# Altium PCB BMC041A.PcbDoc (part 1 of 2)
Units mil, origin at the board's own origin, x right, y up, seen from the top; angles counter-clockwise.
Board outline 3850 x 3650 mil, 6 copper layers (Top Layer, MidLayer1, MidLayer2, MidLayer3, MidLayer4, Bottom Layer), stack 62.8 mil thick; 106 components, 43 nets, 241 pads, 352 vias.
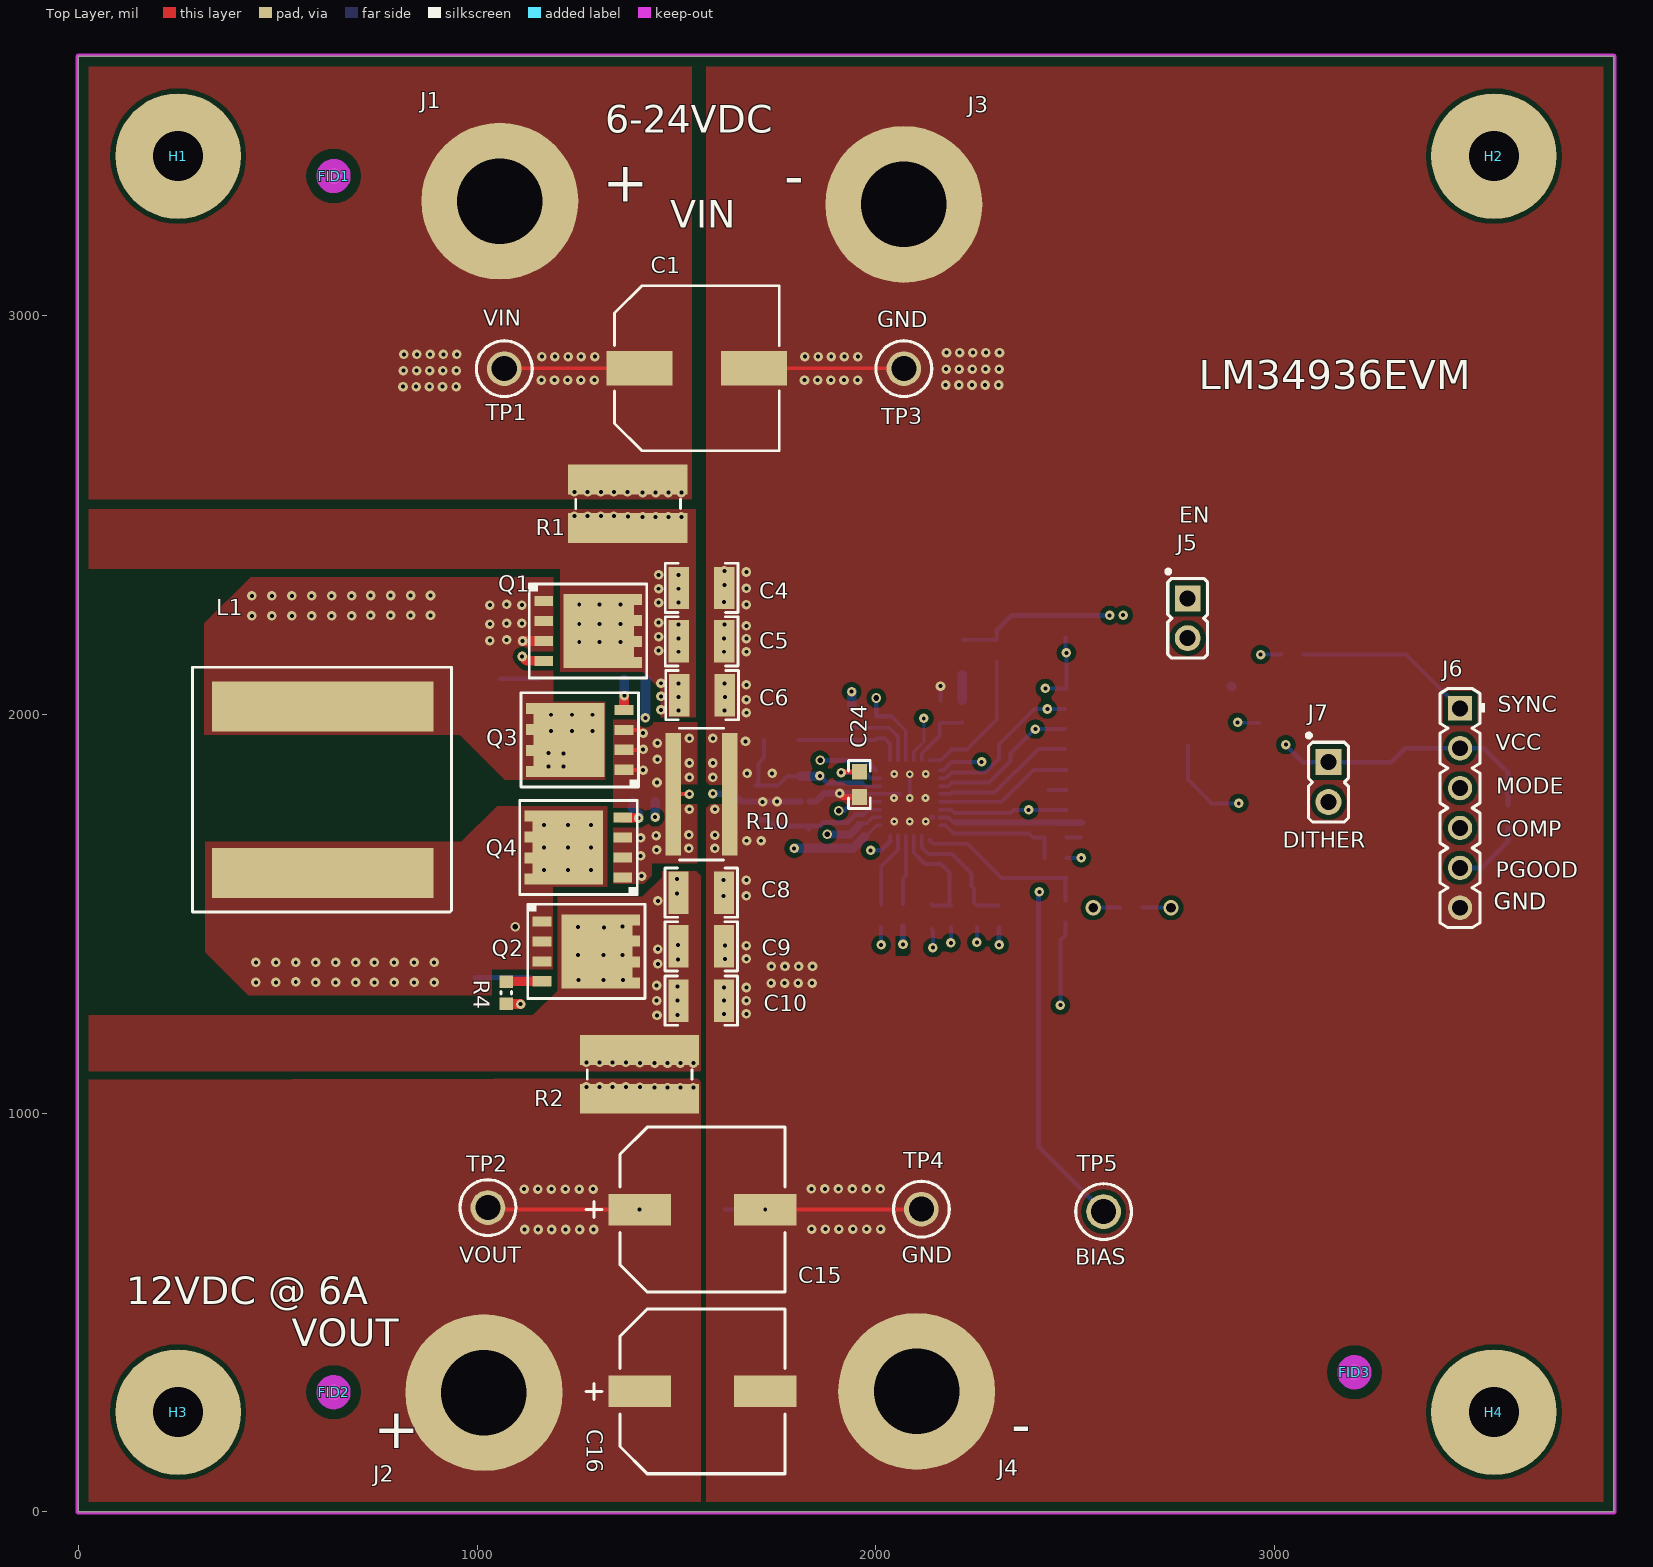
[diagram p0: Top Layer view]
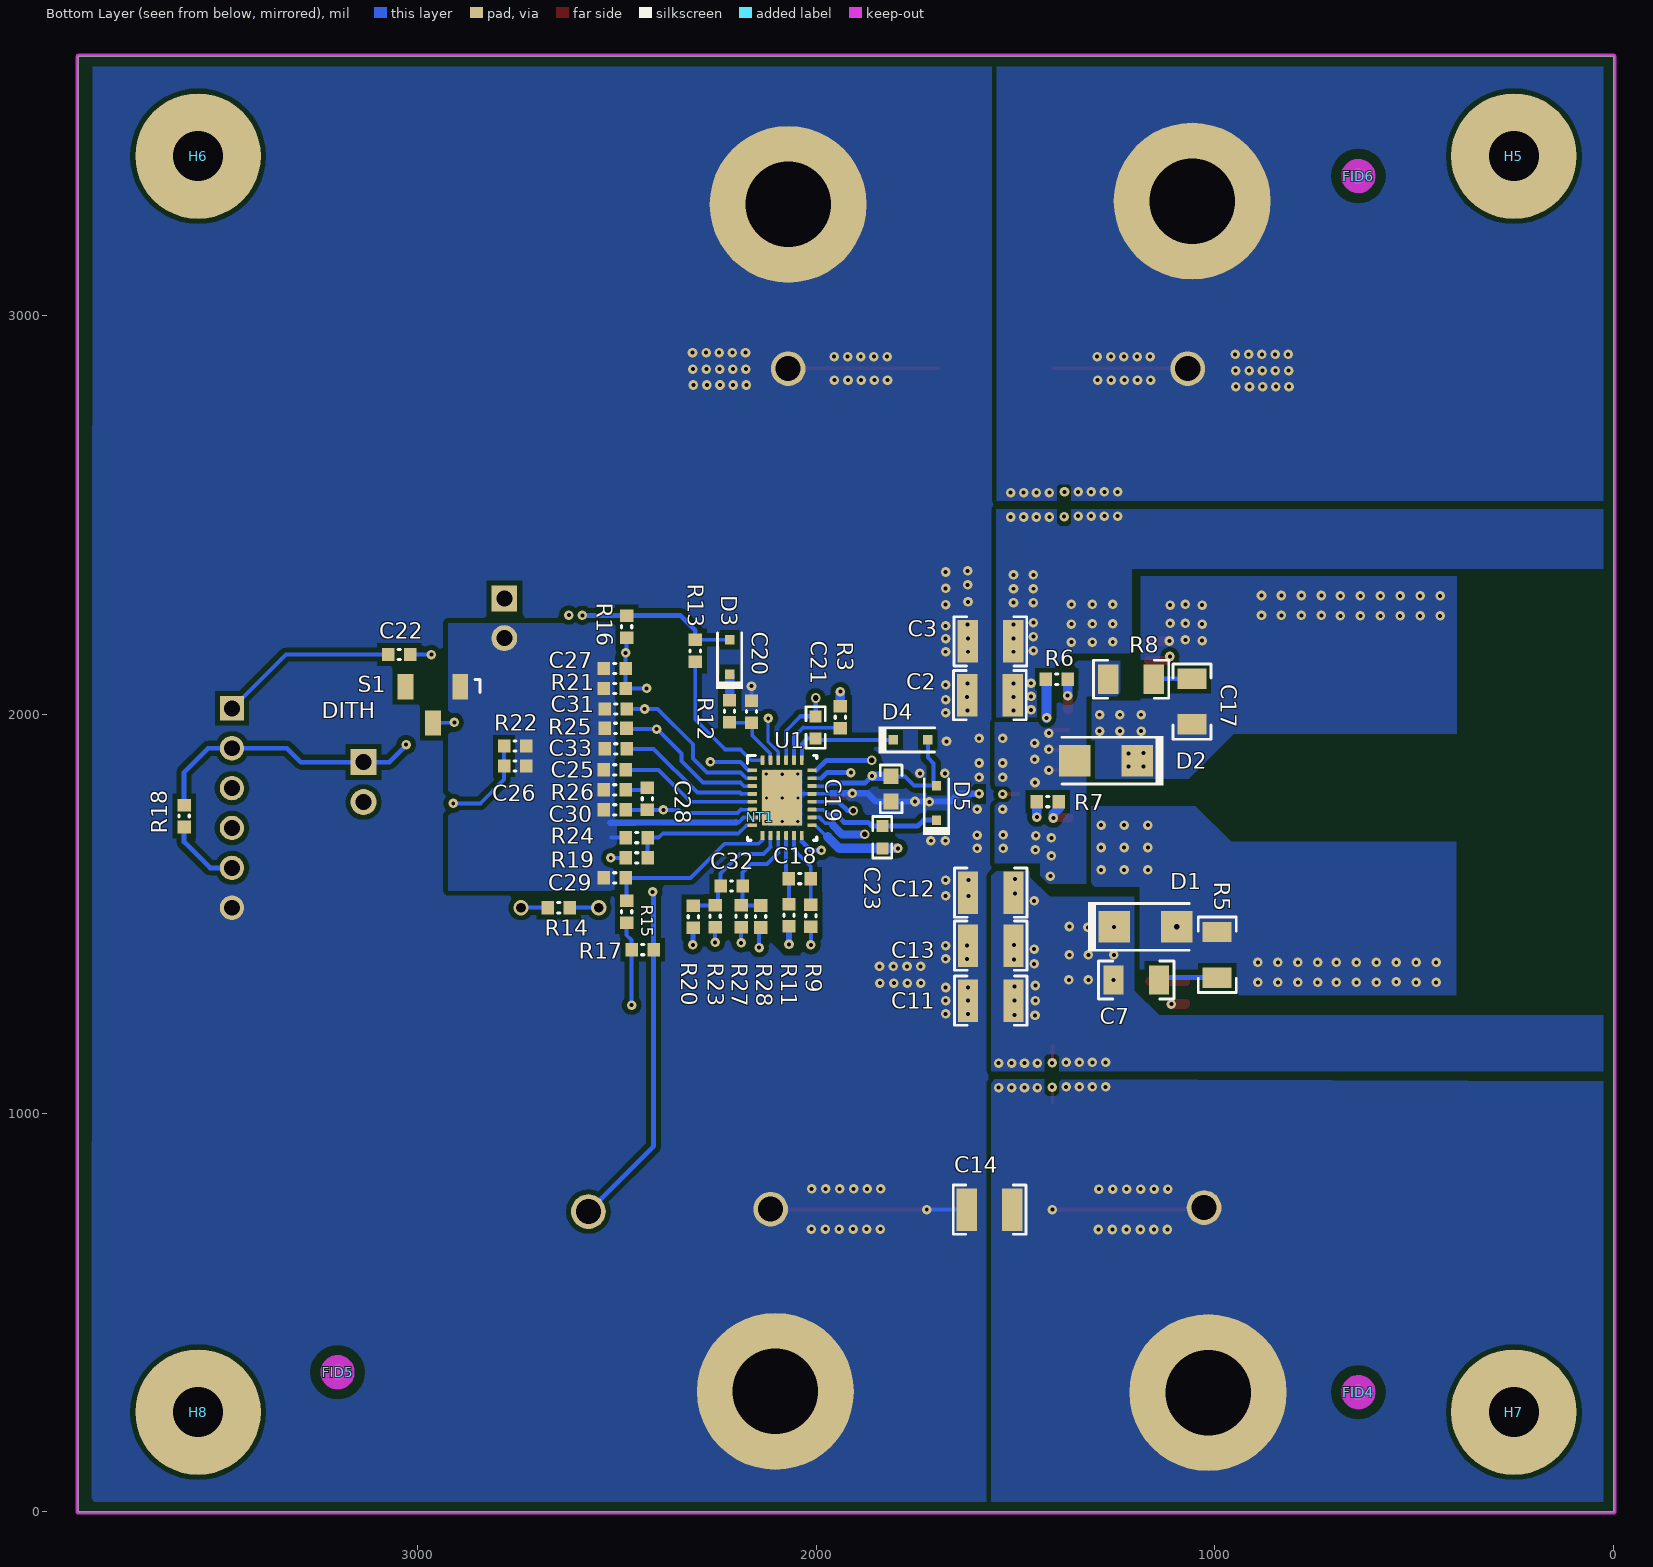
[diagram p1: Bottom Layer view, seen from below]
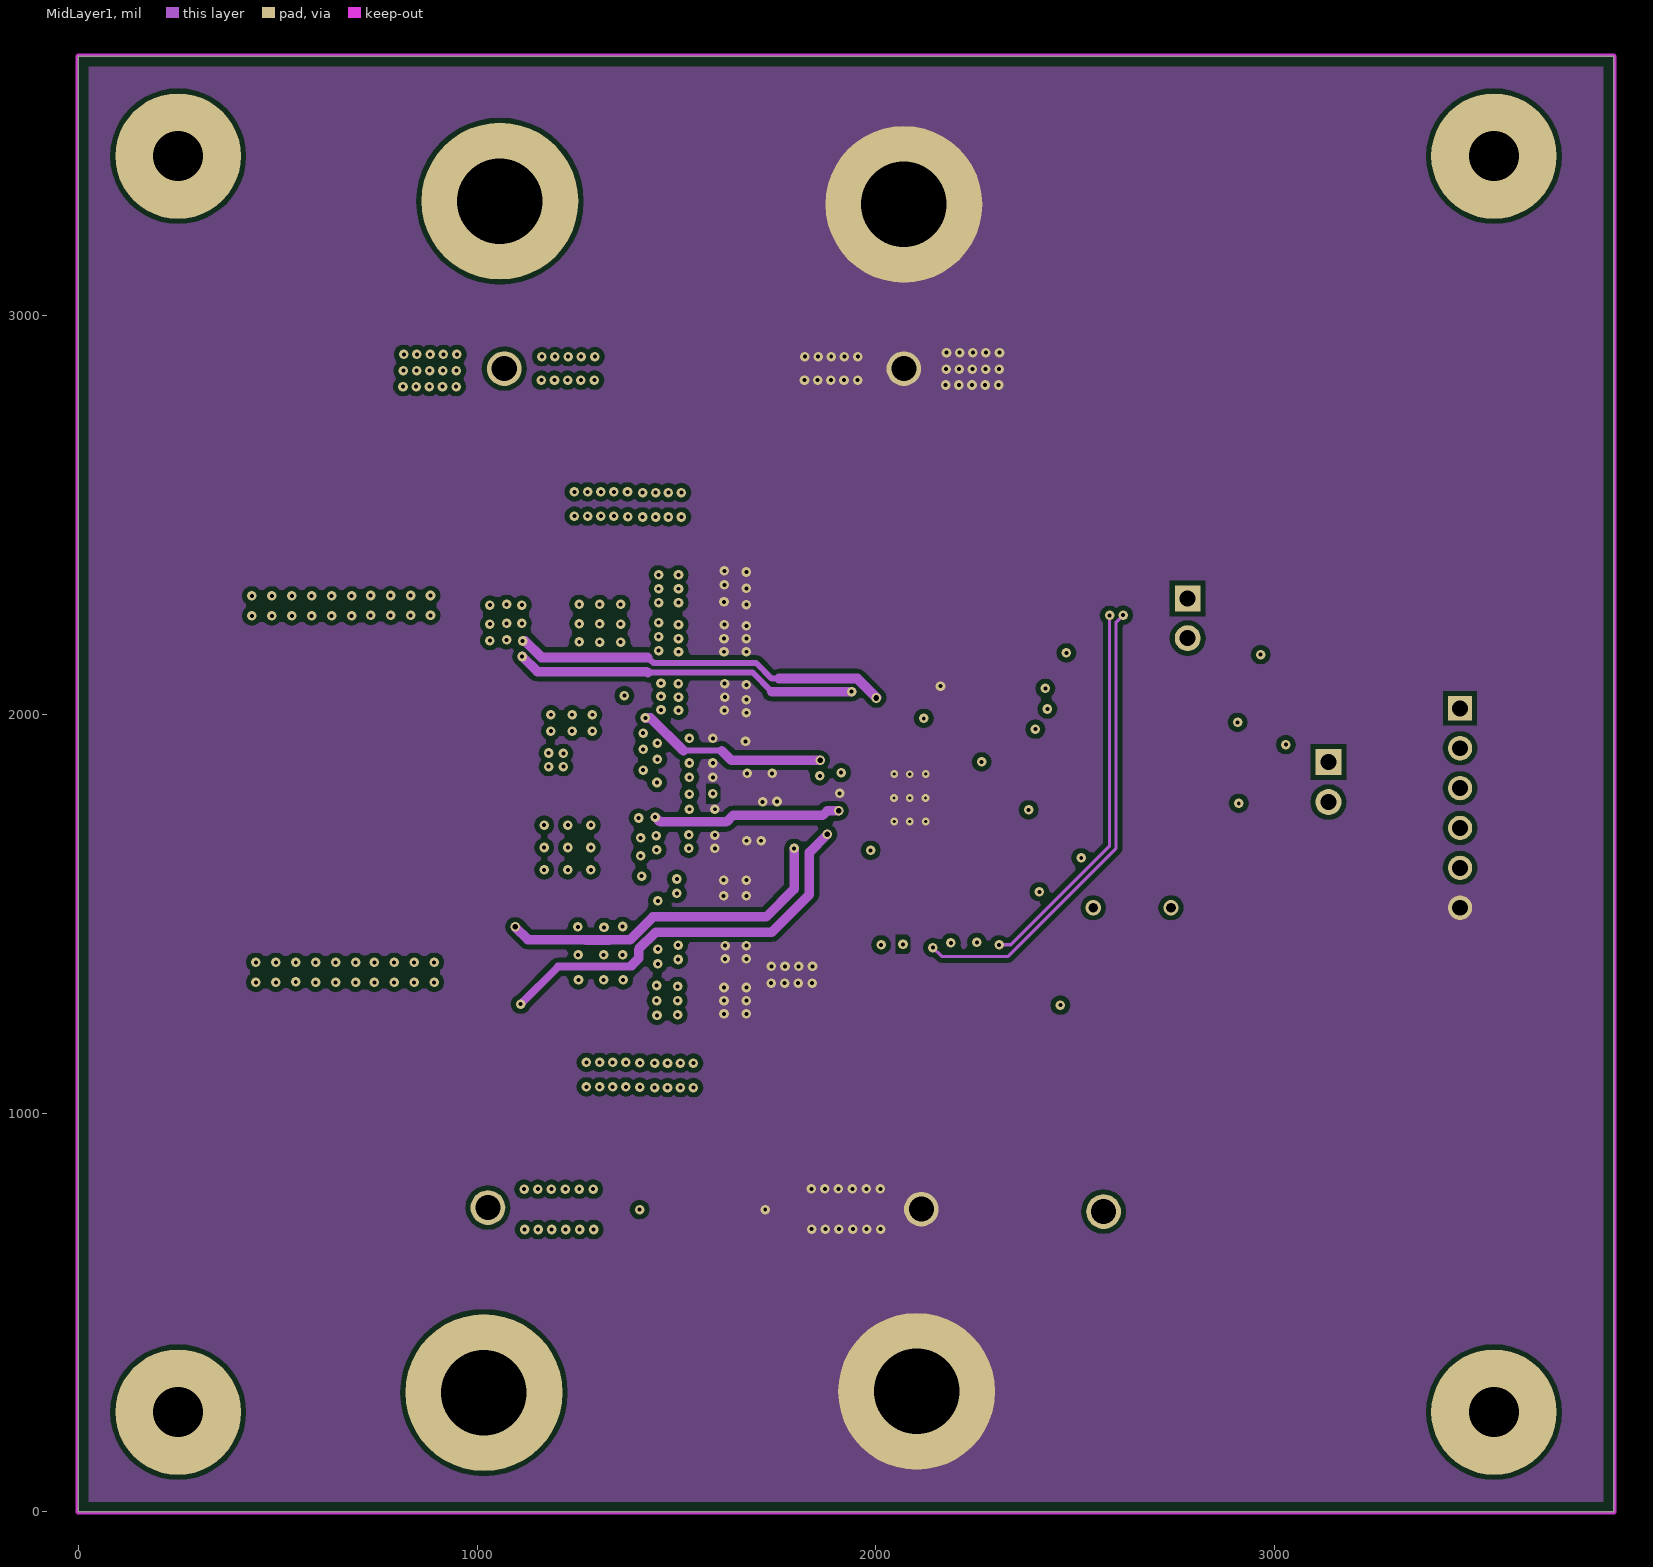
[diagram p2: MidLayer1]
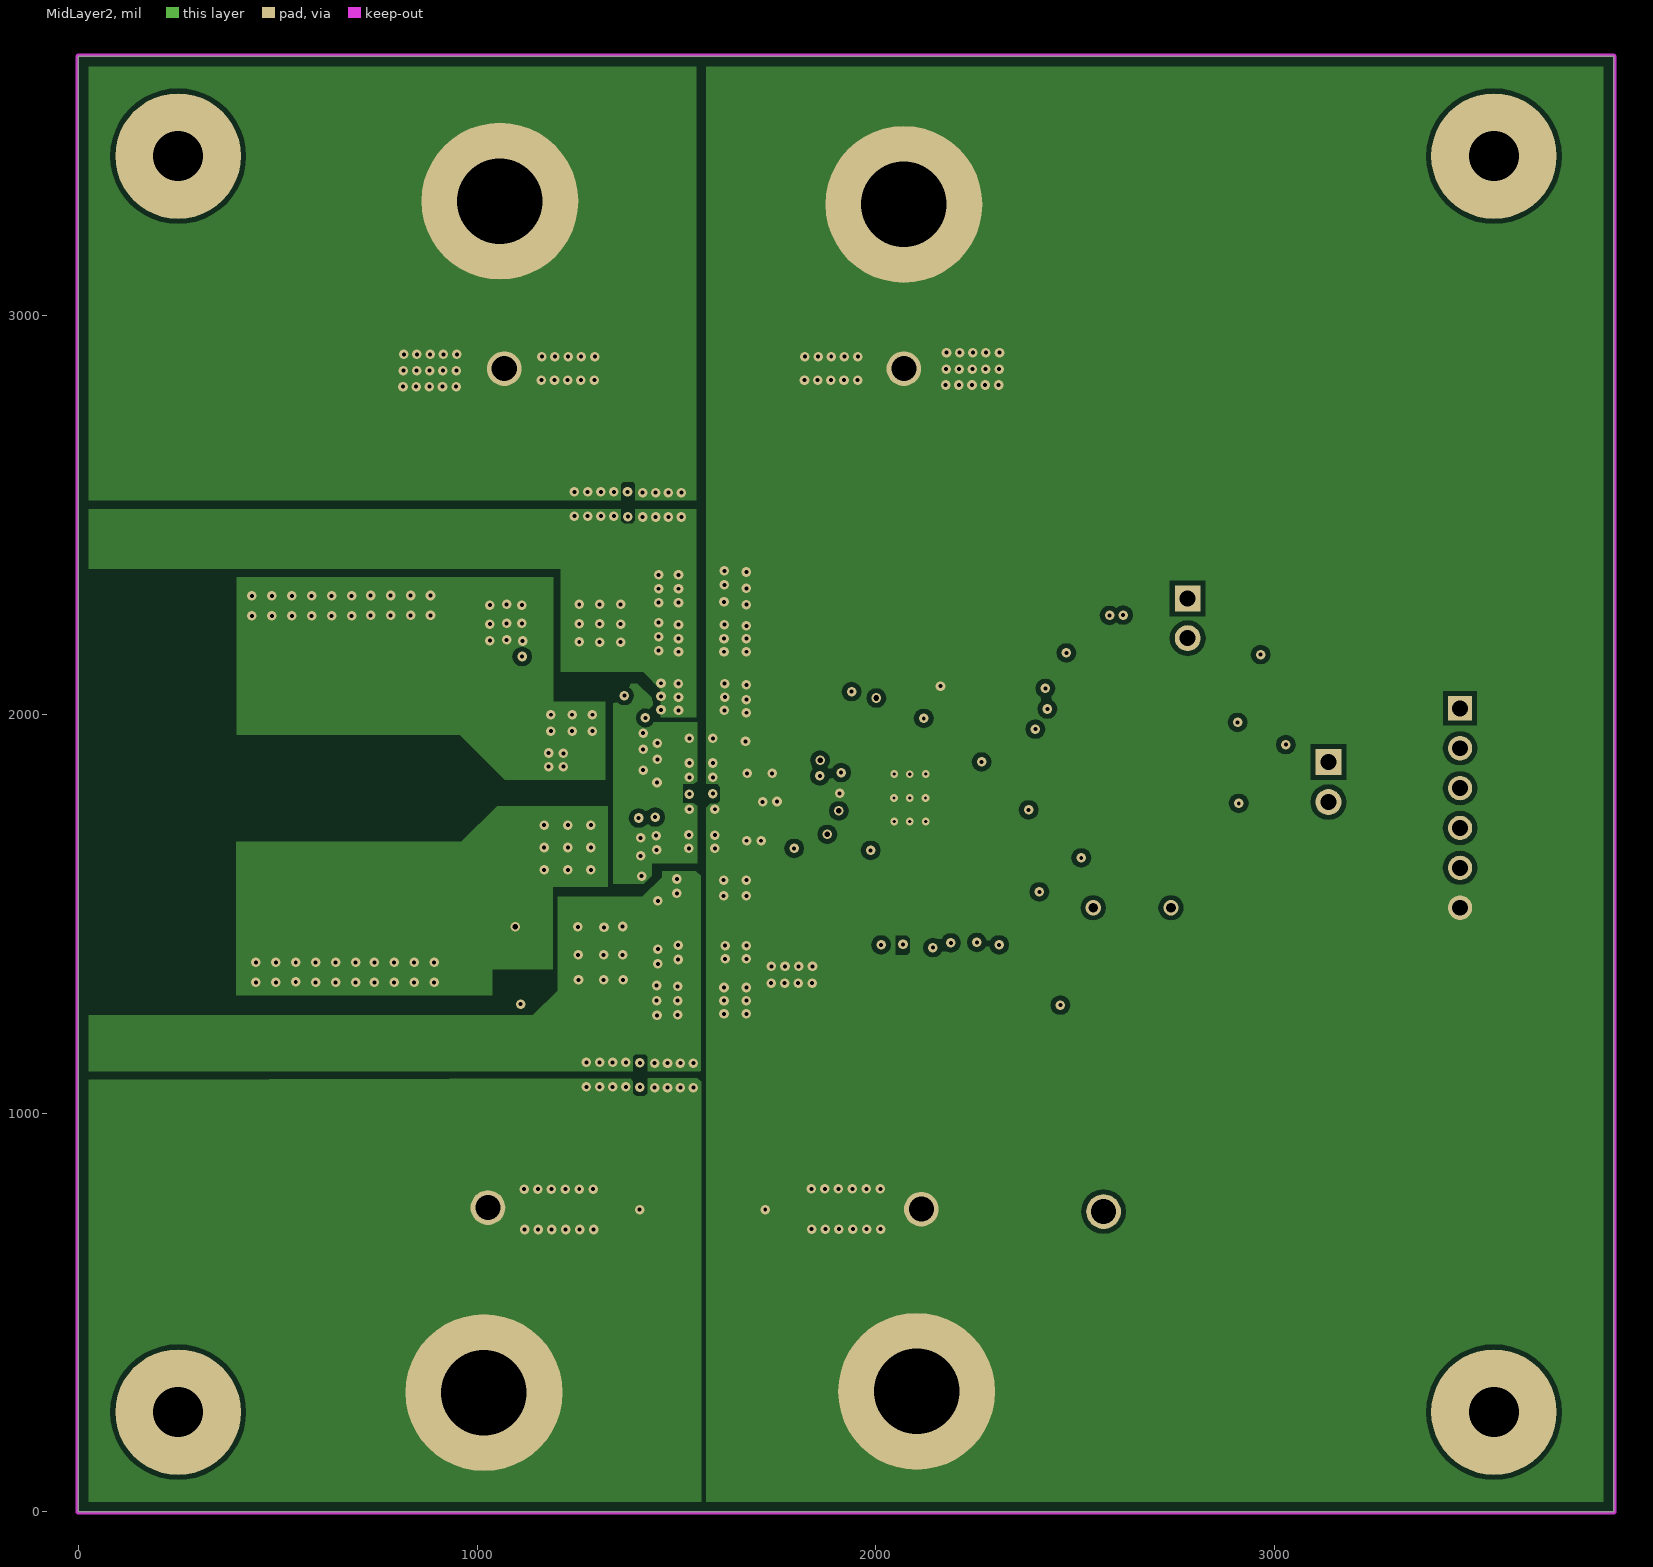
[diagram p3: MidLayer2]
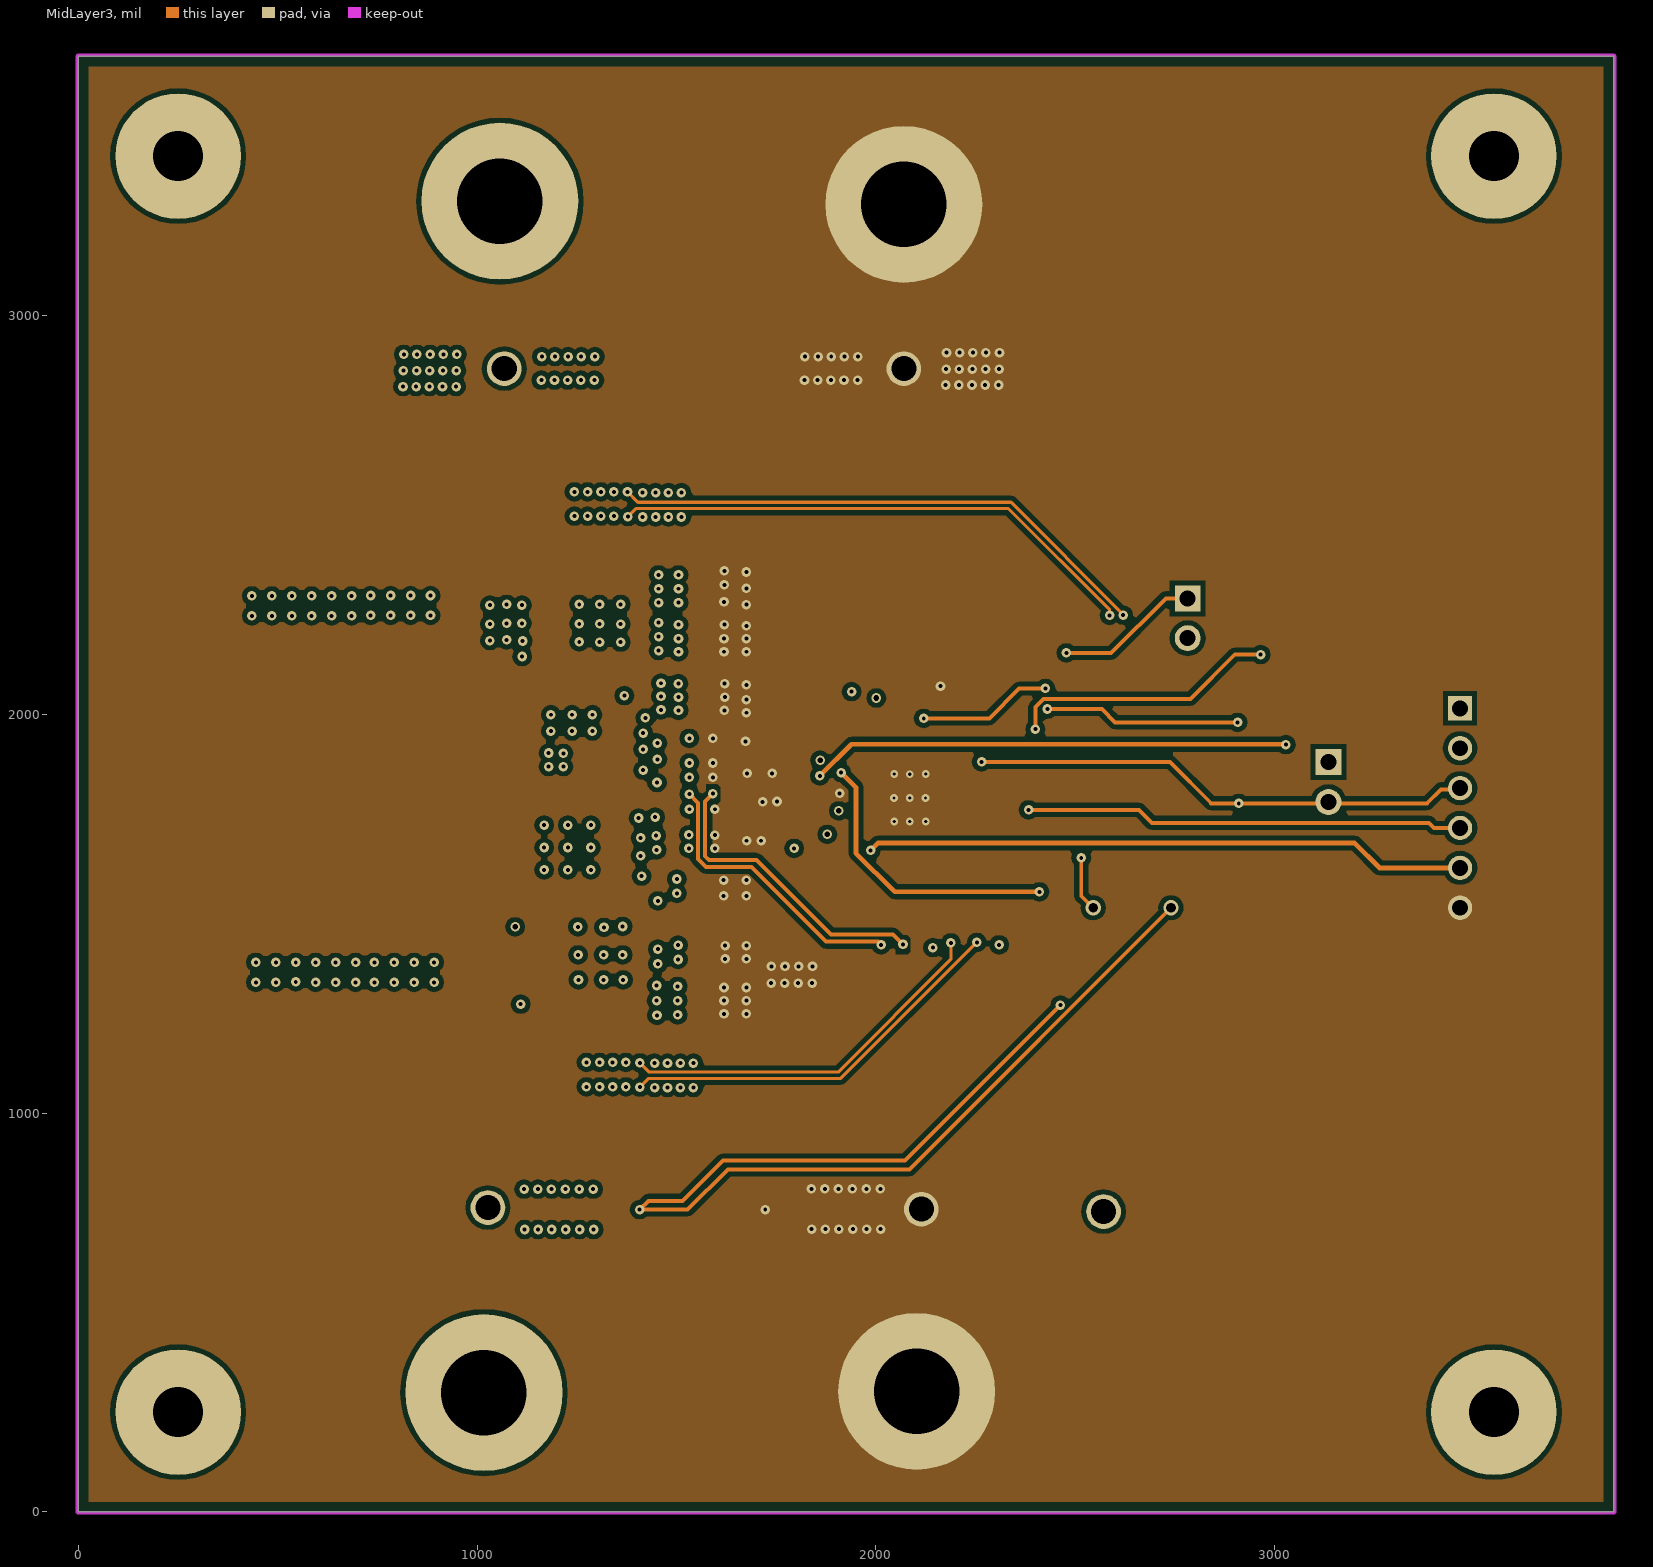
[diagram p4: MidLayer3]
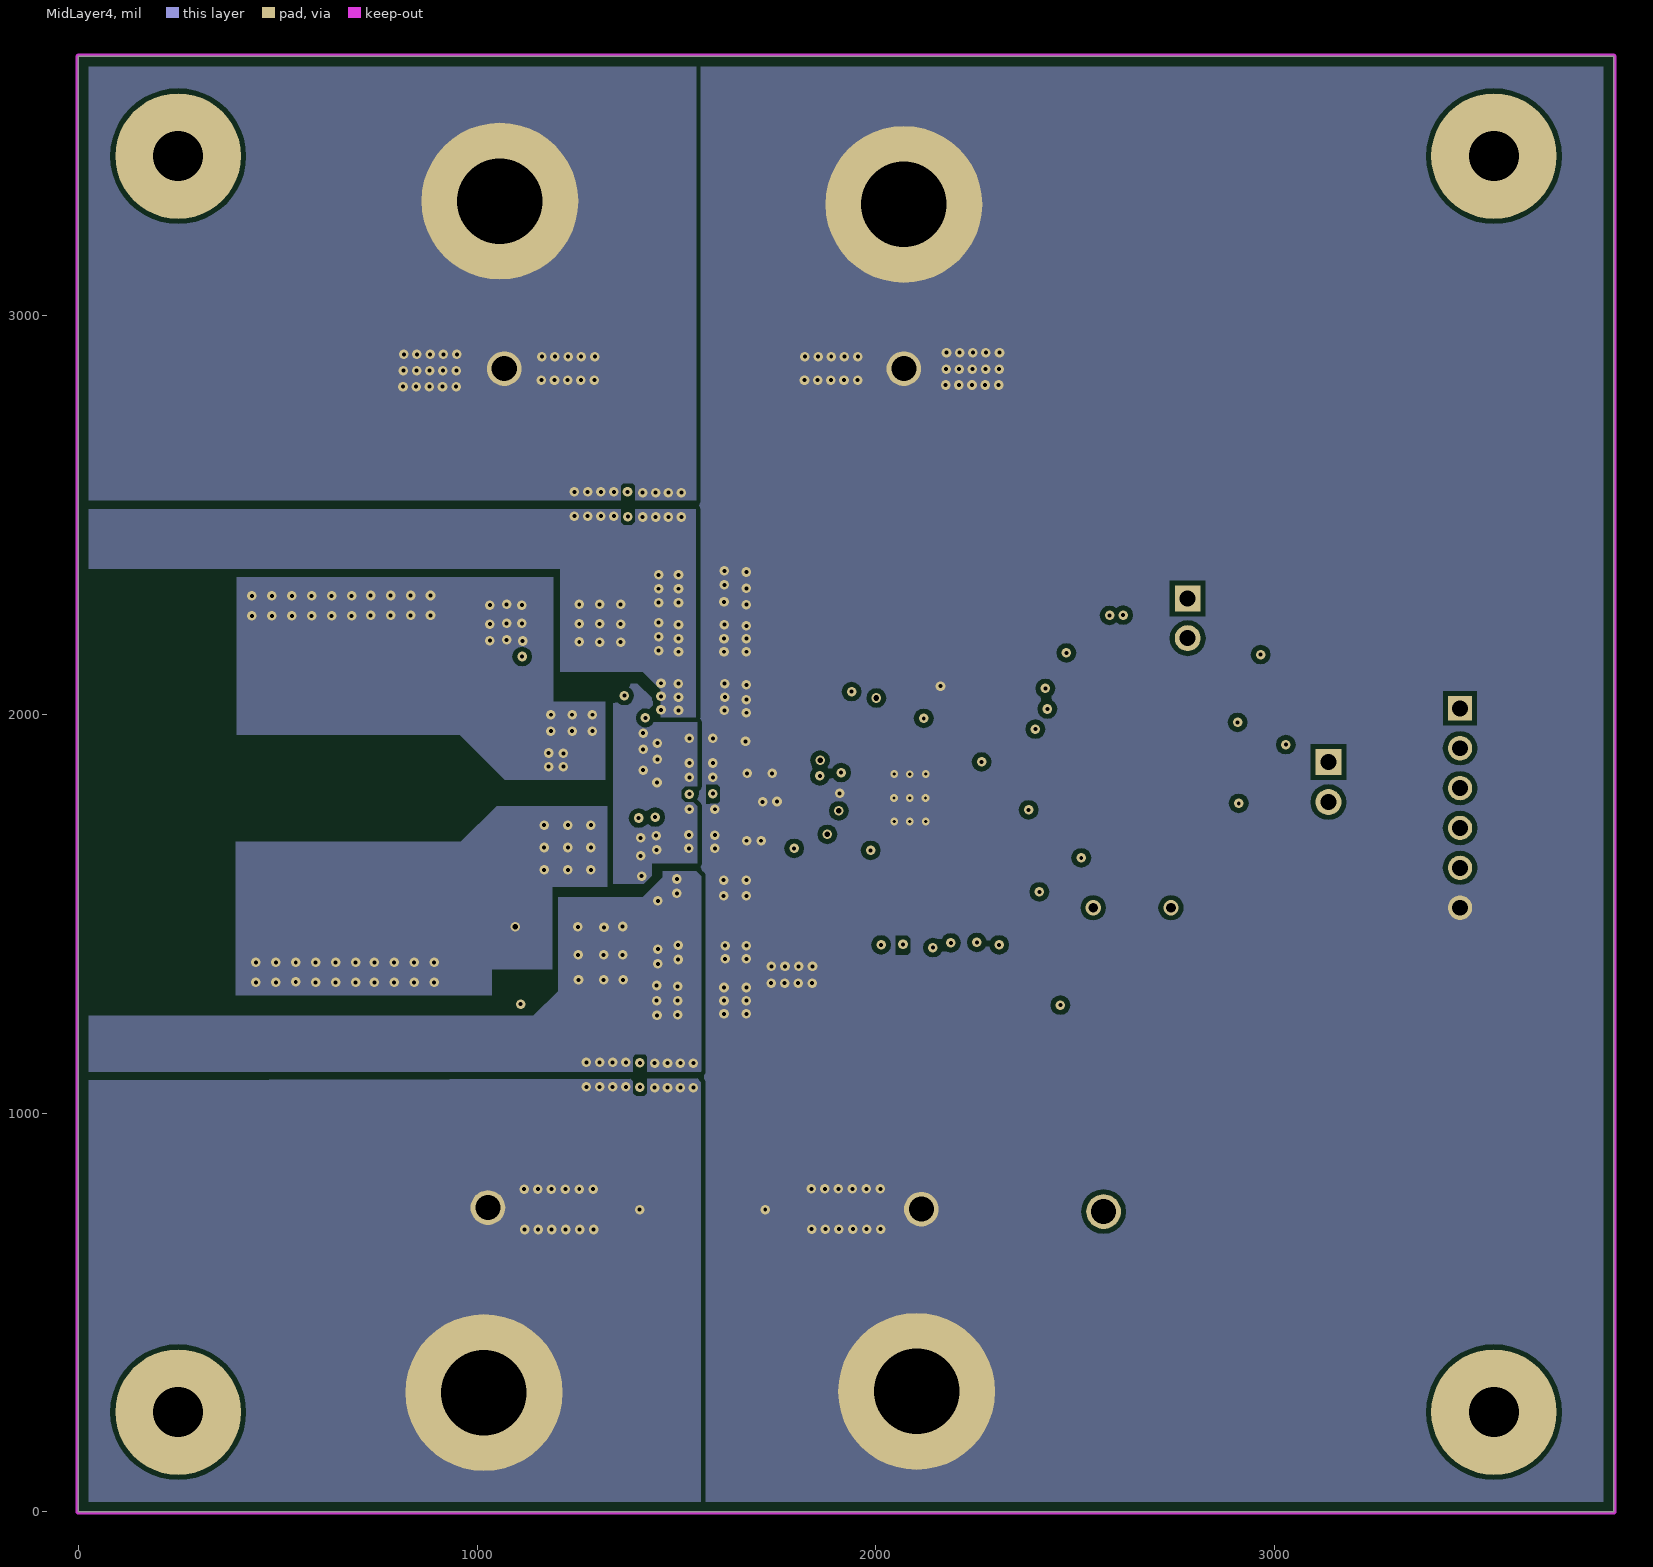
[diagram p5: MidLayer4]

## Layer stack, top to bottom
Top Solder: solder mask 0.4, Solder Resist, Dk 3.5
Top Layer: signal copper 2.8
Dielectric1: prepreg 8, FR-4, Dk 4.2
MidLayer1: signal copper 2.8
Dielectric2: prepreg 10, FR-4, Dk 4.8
MidLayer2: signal copper 2.8
Dielectric3: core 10, FR-4, Dk 4.2
MidLayer3: signal copper 2.8
Dielectric4: prepreg 10, FR-4, Dk 4.8
MidLayer4: signal copper 2.8
Dielectric5: prepreg 8, FR-4, Dk 4.2
Bottom Layer: signal copper 2.8
Bottom Solder: solder mask 0.4, Solder Resist, Dk 3.5

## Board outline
0,0 3850,0 3850,3650 0,3650

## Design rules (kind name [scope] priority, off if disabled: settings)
AcuteAngle [All] p1: minimum=4.50000000000000E+0001 checktracksonly=FALSE
AssemblyTestPointUsage [All] p1: valid=2
Clearance Clearance_FiducialMark [IsKeepOut AND InComponentClass('FiducialMark') vs IsPad AND InComponentClass('FiducialMark')] p1: gap=0 ignorepadtopadclearanceinfootprint=TRUE
Clearance Clearance_BoardEdge_MountingHoles [OnCopper and InComponentClass('Mounting Holes') vs KeepOut] p2: gap=40 ignorepadtopadclearanceinfootprint=FALSE except(0: Arc-Hole Track-Hole SMDPad-Hole THPad-Hole Via-Hole Fill-Hole Poly-Hole Region-Hole Text-Hole)
Clearance Clearance_BoardEdge_Poly [OnCopper and InPoly vs KeepOut] p3: gap=25 ignorepadtopadclearanceinfootprint=FALSE except(0: Arc-Hole Track-Hole SMDPad-Hole THPad-Hole Via-Hole Fill-Hole Poly-Hole Region-Hole Text-Hole)
Clearance Clearance_BoardEdge [OnCopper and Not InComponentClass('Logo') and not InComponentClass('FiducialMark') and not InRegion(1000,500,4000,800) and Not IsKeepout vs KeepOut] p4: gap=47 ignorepadtopadclearanceinfootprint=FALSE except(0: Arc-Hole Track-Hole SMDPad-Hole THPad-Hole Via-Hole Fill-Hole Poly-Hole Region-Hole Text-Hole)
Clearance Clearance_Poly [InPolygon] p5: gap=12 ignorepadtopadclearanceinfootprint=FALSE except(0: Arc-Hole Track-Hole SMDPad-Hole THPad-Hole Via-Hole Fill-Hole Poly-Hole Region-Hole Text-Hole)
Clearance [All] p6: gap=7.87 ignorepadtopadclearanceinfootprint=FALSE except(0: Arc-Hole Track-Hole SMDPad-Hole THPad-Hole Via-Hole Fill-Hole Poly-Hole Region-Hole Text-Hole)
ComponentClearance ComponentClearance_nettie [HasFootprint('Net-Tie_10mil') vs HasFootprint('RHF0028A')] p1: gap=0 collisioncheckmode=3 verticalgap=0 showdistances=FALSE
ComponentClearance ComponentClearance_Shunt [InComponentClass('Header') vs InComponentClass('Shunt')] p2: gap=0 collisioncheckmode=3 verticalgap=0 showdistances=FALSE
ComponentClearance ComponentClearance_MountingHoles_FiducialMarks [InComponentClass('Mounting Holes') vs InComponentClass('FiducialMark')] p3: gap=42 collisioncheckmode=3 verticalgap=10 showdistances=FALSE
ComponentClearance ComponentClearance_Logo [InComponentClass('Logo')] p4: gap=50 collisioncheckmode=3 verticalgap=10 showdistances=FALSE
ComponentClearance ComponentClearance_ScrewToNut [(HasFootprint('NY PMS 440 0025 PH')) vs (HasFootprint('Keystone_1902C'))] p5: gap=5 collisioncheckmode=3 verticalgap=10 showdistances=FALSE
ComponentClearance ComponentClearance_MountingHoles [InComponentClass('Mounting Holes')] p6: gap=200 collisioncheckmode=3 verticalgap=100 showdistances=FALSE
ComponentClearance ComponentClearance_SmallPassives [HasFootprint('0201*') or HasFootprint('0402*') or HasFootprint('0508') or HasFootprint('0603*') or HasFootprint('0612') or HasFootprint('0805*') or HasFootprint('0815*') or HasFootprint('0830*') or HasFootprint('1206*') or HasFootprint('1210*') or HasFootprint('1808*') or HasFootprint('1812*') or HasFootprint('1825*') or HasFootprint('2010*') or HasFootprint('2220*') or HasFootprint('2225*') or HasFootprint('2512*') or HasFootprint('2728*') or HasFootprint('3518*') vs HasFootprint('0201*') or HasFootprint('0402*') or HasFootprint('0508') or HasFootprint('0603*') or HasFootprint('0612') or HasFootprint('0805*') or HasFootprint('0815*') or HasFootprint('0830*') or HasFootprint('1206*') or HasFootprint('1210*') or HasFootprint('1808*') or HasFootprint('1812*') or HasFootprint('1825*') or HasFootprint('2010*') or HasFootprint('2220*') or HasFootprint('2225*') or HasFootprint('2512*') or HasFootprint('2728*') or HasFootprint('3518*')] p7: gap=10 collisioncheckmode=3 verticalgap=10 showdistances=FALSE
ComponentClearance ComponentClearance_THtoSMT [IsThruComponent vs IsSMTComponent] p8: gap=40 collisioncheckmode=3 verticalgap=30 showdistances=FALSE
ComponentClearance ComponentClearance_THtoTH [IsThruComponent vs IsThruComponent] p9: gap=25 collisioncheckmode=3 verticalgap=15 showdistances=FALSE
ComponentClearance [All] p10: gap=40 collisioncheckmode=3 verticalgap=10 showdistances=FALSE
DiffPairsRouting [All] p1: maxlimit=100 minlimit=10 mostfreqgap=10 toplayer_minwidth=15 toplayer_maxwidth=15 toplayer_prefwidth=15 midlayer1_minwidth=15 midlayer1_maxwidth=15 midlayer1_prefwidth=15 midlayer2_minwidth=15 midlayer2_maxwidth=15 midlayer2_prefwidth=15 midlayer3_minwidth=15 midlayer3_maxwidth=15 midlayer3_prefwidth=15 midlayer4_minwidth=15 midlayer4_maxwidth=15 midlayer4_prefwidth=15 bottomlayer_minwidth=15 bottomlayer_maxwidth=15 bottomlayer_prefwidth=15 maxuncoupledlength=1000
FabricationTestPointUsage TestPointUsage [All] p1: valid=2 allowmultiple=FALSE
FabricationTestpoint Testpoint [All] p1: side=3 testpointundercomponent=TRUE minsize=40 maxsize=100 preferedsize=60 minholesize=0 maxholesize=40 preferedholesize=32 testpointgrid=1 allowsidetop=TRUE allowsidebottom=TRUE usegrid=TRUE gridtolerance=0.01
FanoutControl Fanout_LCC [IsLCC] p1: bgadir=Out bgaviamode=Centered fanoutstyle=Auto fanoutdirection=Alternating viagrid=1 // Fanout_LCC (Default Rule)
FanoutControl Fanout_BGA [IsBGA] p2: bgadir=Out bgaviamode=Centered fanoutstyle=Auto fanoutdirection=Alternating viagrid=1 // Fanout_BGA (Default Rule)
FanoutControl Fanout_Default [All] p4: bgadir=Out bgaviamode=Centered fanoutstyle=Auto fanoutdirection=Alternating viagrid=1 // Fanout_Default (Default Rule)
FanoutControl Fanout_Small [(CompPinCount < 5)] p5: bgadir=Out bgaviamode=Centered fanoutstyle=Auto fanoutdirection=OutThenIn viagrid=1 // Fanout_Small (Default Rule)
HoleSize [All] p1: absolutevalues=TRUE maxlimit=280 minlimit=7.87 maxpercent=80.000 minpercent=20.000
MinimumAnnularRing MinimumAnnularRing_ThermalPadVias [IsVia and InAnyComponent] p1: minimumring=3.94
MinimumAnnularRing [All] p2: minimumring=5
MinimumSolderMaskSliver MinimumSolderMaskSliver_Logo [InComponentClass('Logo') vs InComponentClass('Logo')] p1: minsoldermaskwidth=0.7
MinimumSolderMaskSliver [All] p2: minsoldermaskwidth=3.94
PlaneConnect [All] p1: planeconnectstyle=Relief reliefexpansion=10 reliefentries=4 reliefconductorwidth=10 reliefairgap=10
PolygonConnect [All] p1: connectstyle=Direct reliefconductorwidth=10 reliefentries=4 polygonreliefangle="90 Angle" airgapwidth=10
RoutingVias ThermalPadVias [IsVia and InAnyComponent] p1: holewidth=7.87 width=19.68 viastyle="Through Hole" minholewidth=7.87 minwidth=15.75 maxholewidth=12.99 maxwidth=23.62
RoutingVias [All] p2: holewidth=10 width=24 viastyle="Through Hole" minholewidth=7.87 minwidth=13.78 maxholewidth=40 maxwidth=65
SMDToCorner [All] p1: distance=30000
SilkToBoardRegionClearance [NOT ((IsComment OR IsDesignator) AND (Hide <> 'FAIL')) AND NOT InRegion (100,500,4000,8000)] p1:
SilkToSilkClearance [All] p1: silktosilkclearance=5
SilkToSolderMaskClearance SilkscreenOverComponentPads [IsPad] p1: minsilkscreentomaskgap=5 clearancetoexposedcopper=TRUE
SolderMaskExpansion [All] p1: expansion=1.97
Width [All] p1: maxlimit=100 minlimit=6 preferedwidth=10 checkconnectedcopper=TRUE
15 further rules are at their usual default settings.

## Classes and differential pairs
component class BMC041A: C1 C2 C3 C4 C5 C6 C7 C8 C9 C10 C11 C12 C13 C14 C15 C16 C17 C18 C19 C20 C21 C22 C23 C24 C25 C26 C27 C28 C29 C30 C31 C32 C33 D1 D2 D3 D4 D5 J1 J2 J3 J4 J5 J6 J7 L1 NT1 Q1 Q2 Q3 Q4 R1 R2 R3 R4 R5 R6 R7 R8 R9 R10 R11 R12 R13 R14 R15 R16 R17 R18 R19 R20 R21 R22 R23 R24 R25 R26 R27 R28 S1 TP1 TP2 TP3 TP4 TP5 U1
component class AssemblyNote: ZZ2 ZZ3 ZZ4 ZZ5 ZZ6 ZZ7
component class FiducialMark: FID1 FID2 FID3 FID4 FID5 FID6
component class BMC041A-HW: FID1 FID2 FID3 FID4 FID5 FID6 H1 H2 H3 H4 H5 H6 H7 H8 ZZ2 ZZ3 ZZ4 ZZ5 ZZ6 ZZ7
component class "Mounting Holes": H1 H2 H3 H4
component class Header: J5 J6 J7

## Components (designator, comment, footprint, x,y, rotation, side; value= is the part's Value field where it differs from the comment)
C1 "Cap_Polarized" CR_1000x1000 1551,2868 r0 top value=68uF
C2 "Capacitor" 1210_220 1564,2048 r0 bottom value=4.7uF
C3 "Capacitor" 1210_220 1563,2183 r0 bottom value=4.7uF
C4 "Capacitor" 1210_220 1563,2317 r0 top value=4.7uF
C5 "Capacitor" 1210_220 1563,2183 r0 top value=4.7uF
C6 "Capacitor" 1210_220 1564,2048 r0 top value=4.7uF
C7 "Capacitor" 1206 1197,1334 r180 bottom value=100pF
C8 "Capacitor" 1210_270 1562,1553 r0 top value=10uF
C9 "Capacitor" 1210_270 1562,1418 r0 top value=10uF
C10 "Capacitor" 1210_270 1562,1282 r0 top value=10uF
C11 "Capacitor" 1210_270 1562,1282 r0 bottom value=10uF
C12 "Capacitor" 1210_270 1562,1553 r0 bottom value=10uF
C13 "Capacitor" 1210_270 1562,1420 r0 bottom value=10uF
C14 "Capacitor" 1210_270 1565,758 r0 bottom value=10uF
C15 "Cap_Polarized" CR_1000x1270 1565,758 r0 top value=180uF
C16 "Cap_Polarized" CR_1000x1270 1565,302 r0 top value=180uF
C17 "Capacitor" 1206 1057,2032 r90 bottom value=100pF
C18 "Capacitor" 0603L 2041,1588 r0 bottom value=47pF
C19 "Capacitor" 0603 1812,1813 r90 bottom value=1uF
C20 "Capacitor" 0603L 2162,2007 r90 bottom value=0.1uF
C21 "Capacitor" 0603_HV 2001,1967 r270 bottom value=0.1uF
C22 "Capacitor" 0603L 3045,2150 r180 bottom value=100pF
C23 "Capacitor" 0603_HV 1834,1692 r270 bottom value=0.1uF
C24 "Capacitor" 0603 1958.62,1824.19 r270 top value=0.1uF
C25 "Capacitor" 0603L 2505,1860.63 r0 bottom value=0.1uF
C26 "47pF" 0603L 2755,1870.63 r180 bottom
C27 "47pF" 0603L 2505,2115 r0 bottom
C28 "Capacitor" 0603L 2423.19,1788.02 r90 bottom value=0.022uF
C29 "Capacitor" 0603L 2505,1590 r0 bottom value=100pF
C30 "Capacitor" 0603L 2505,1760.63 r0 bottom value=100pF
C31 "Capacitor" 0603L 2502.2,2013.43 r0 bottom value=0.022uF
C32 "Capacitor" 0603L 2212,1569.7 r180 bottom value=1uF
C33 "Capacitor" 0603L 2502.2,1913.43 r0 bottom value=100pF
D1 "20V" SMA 1174,1467 r180 bottom
D2 "60V" SMA 1273,1884 r0 bottom
D3 "60V" SOD-323F 2217,2144 r90 bottom
D4 "100V" SOD-323 1763,1936 r180 bottom
D5 "100V" SOD-323 1698,1778 r90 bottom
FID1 "Fiducial" Fiducial10-20 640,3350 r0 top
FID2 "Fiducial" Fiducial10-20 640,300 r0 top
FID3 "Fiducial" Fiducial10-20 3200,350 r0 top
FID4 "Fiducial" Fiducial10-20 640,300 r180 bottom
FID5 "Fiducial" Fiducial10-20 3200,350 r180 bottom
FID6 "Fiducial" Fiducial10-20 640,3350 r180 bottom
H1 "NY PMS 440 0025 PH" "NY PMS 440 0025 PH" 250,3400 r0 top locked
H2 "NY PMS 440 0025 PH" "NY PMS 440 0025 PH" 3550,3400 r0 top locked
H3 "NY PMS 440 0025 PH" "NY PMS 440 0025 PH" 250,250 r0 top locked
H4 "NY PMS 440 0025 PH" "NY PMS 440 0025 PH" 3550,250 r0 top locked
H5 "Nut" Keystone_1902C 250,3400 r180 bottom locked
H6 "Nut" Keystone_1902C 3550,3400 r180 bottom locked
H7 "Nut" Keystone_1902C 250,250 r180 bottom locked
H8 "Nut" Keystone_1902C 3550,250 r180 bottom locked
J1 "575-4" Keystone_575-4 1057,3287 r90 top
J2 "575-4" Keystone_575-4 1017,299 r90 top
J3 "575-4" Keystone_575-4 2070,3279 r90 top
J4 "575-4" Keystone_575-4 2102,302 r90 top
J5 "Header_2x1" Sullins_PBC02SAAN 2782,2241 r0 top
J6 "PBC06SAAN" Sullins_PxC06SAAN 3465,1765 r270 top
J7 "Header_2x1" Sullins_PBC02SAAN 3135,1830 r0 top
L1 "Inductor_Iron" XAL1510 613,1811 r270 top value=4.7uH
NT1 "Net-Tie" Net-Tie_10mil 2141,1741.42 r0 bottom net-tie
Q1 "BSC039N06NS" PG-TDSON-8 1278,2209 r0 top value=60V
Q2 "BSC039N06NS" PG-TDSON-8 1274,1405.5 r0 top value=60V
Q3 "BSC039N06NS" PG-TDSON-8 1257,1936 r180 top value=60V
Q4 "BSC039N06NS" PG-TDSON-8 1254,1666 r180 top value=60V
R1 "Resistor" 2512_WIDE_VISHAY 1378,2528 r270 top value=0
R2 "Resistor" 2512_WIDE_VISHAY 1407,1097 r270 top value=0
R3 "Resistor" 0603L 1939,1993 r270 bottom value=0
R4 "Resistor" 0603L 1073,1302 r270 top value=0
R5 "Resistor" 1206 994,1397 r270 bottom value=10
R6 "Resistor" 0603L 1396,2088 r0 bottom value=0
R7 "Resistor" 0603L 1419,1781 r0 bottom value=0
R8 "Resistor" 1206 1210,2088 r180 bottom value=10
R9 "Resistor" 0603L 2013,1495 r270 bottom value=100
R10 "Resistor" 3015 1562.7,1800 r180 top value=0.008
R11 "Resistor" 0603L 2068,1496 r270 bottom value=100
R12 "Resistor" 0603L 2217,2008 r90 bottom value=10.0
R13 "CRCW06032K00FKEA" 0603L 2303,2159 r90 bottom value=2.00k
R14 "Resistor" 0603L 2645,1515 r180 bottom value=10.0
R15 "Resistor" 0603L 2475,1505 r90 bottom value=0
R16 "Resistor" 0603L 2475,2220 r90 bottom value=249k
R17 "Resistor" 0603L 2435,1410 r180 bottom value=0
R18 "Resistor" 0603L 3585,1745 r90 bottom value=10.0k
R19 "Resistor" 0603L 2450,1640 r0 bottom value=280k
R20 "Resistor" 0603L 2308,1492.73 r270 bottom value=100
R21 "Resistor" 0603L 2505,2065 r180 bottom value=59.0k
R22 "Resistor" 0603L 2755,1920.63 r0 bottom value=93.1k
R23 "Resistor" 0603L 2253,1493.43 r270 bottom value=100
R24 "Resistor" 0603L 2449.94,1690.63 r180 bottom value=20.0k
R25 "CRCW060327K4FKEA" 0603L 2503,1965 r180 bottom value=27.4k
R26 "Resistor" 0603L 2505,1810.63 r180 bottom value=10.0k
R27 "Resistor" 0603L 2188,1493.43 r270 bottom value=100
R28 "Resistor" 0603L 2139,1493 r270 bottom value=100
S1 "SW_SPDT_ON-OFF-ON_COM2_1_3" SW_CJS_1201A 2961,2024 r0 bottom
TP1 "5005" Keystone5005 1068,2867 r90 top
TP2 "5005" Keystone5005 1027,763 r90 top
TP3 "5006" Keystone5006 2070,2867 r90 top
TP4 "5006" Keystone5006 2114,759 r90 top
TP5 "5007" Keystone5007 2571,753 r90 top
U1 "LM34936RHFR" RHF0028A 2085,1790.63 r180 bottom
ZZ2 "These assemblies are ESD sensitive, ESD precautions shall be observed." AssemblyNote 105,4447.86 r0 top
ZZ3 "These assemblies must be clean and free from flux and all contaminants. Use of no clean flux is not acceptable." AssemblyNote 105,4363.05 r0 top
ZZ4 "These assemblies must comply with workmanship standards IPC-A-610 Class 2, unless otherwise specified." AssemblyNote 105,4278.24 r0 top
ZZ5 "Remove Kapton tape from switch S1 on PCB Bottom side after final wash." AssemblyNote 105,4193.43 r0 top
ZZ6 "Set S1 switch to Pin1 Position (Towards Pin 1 Silkscreen Mark)" AssemblyNote 105,4108.62 r0 top
ZZ7 "Install Jumper SH-J1 onto J7" AssemblyNote 105,4023.81 r0 top

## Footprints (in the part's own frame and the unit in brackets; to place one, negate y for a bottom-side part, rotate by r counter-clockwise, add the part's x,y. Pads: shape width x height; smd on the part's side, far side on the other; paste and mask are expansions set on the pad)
0603 [mm] "0603 from SM-752 data"
  rect 1x0.95 smd: 1(-0.8,0) 2(0.8,0)
  silkscreen extent -1.52,-0.69 1.52,0.69, body extent -0.87,-0.47 0.87,0.47, height 1
0603_HV [mil] "Ernesto recommended land pattern.  26 mil between pads."
  rect 30x30 smd: 1(-28,0) 2(28,0)
  silkscreen extent -52,-24 52,24, body extent -34,-19 34,19, height 39
0603L [mm] "0603 from SM-752 data"
  rect 0.8x0.85 smd: 1(-0.7,0) 2(0.7,0)
  silkscreen extent -0.07,-0.33 0.07,0.33, body extent -0.87,-0.47 0.87,0.47, height 1
1206 [mm] "1206 from SM-752 data"
  rect 1.3x1.85 smd: 1(-1.45,0) 2(1.45,0)
  silkscreen extent -2.4,-1.21 2.4,1.21, body extent -1.7,-0.9 1.7,0.9, height 1.35
1210_220 [mm] "1210"
  rect 1.3x2.7 smd: 1(-1.45,0) 2(1.45,0)
  silkscreen extent -2.32,-1.57 2.32,1.57, body extent -1.7,-1.35 1.7,1.35, height 2.2
1210_270 [mm] "1210"
  rect 1.3x2.7 smd: 1(-1.45,0) 2(1.45,0)
  silkscreen extent -2.32,-1.57 2.32,1.57, body extent -1.7,-1.35 1.7,1.35, height 2.7
2512_WIDE_VISHAY [mm] "Vishay recommended land pattern"
  rect 1.9x7.6 smd: 1(-1.55,0) 2(1.55,0)
  silkscreen extent -0.3,-3.32 0.3,3.35, body extent -1.7,-3.25 1.7,3.25, height 0.9
3015 [mm] "Susumu recommended land pattern"
  rect 1x7.8 smd: 1(-1.8,0) 2(1.8,0)
  silkscreen extent -1.4,-4.19 1.4,4.19, body extent -2,-3.9 2,3.9, height 0.7
AssemblyNote [mil] "Assembly Note"
CR_1000x1000 [mm] "10 x 10mm:  Nichicon CR series"
  rect 4.2x2.2 smd: 1(-3.65,0) 2(3.65,0)
  silkscreen extent -5.25,-5.25 5.25,5.25, body extent -4.96,-4.99 5,4.99, height 10.01
CR_1000x1270 [mm] "SMD, 2-Leads, Dia 10.5mm, Pin Spacing 8mm"
  rect 4x2 smd: 1(-4,0) 2(4,0)
  silkscreen extent -7.4,-5.25 5.25,5.25, body extent -5.25,-5.25 5.25,5.25, height 12.71
Fiducial10-20 [mm]
  round 1 smd mask+0.5: 1(0,0)
  Top Layer keep-out circle w1.178: c0,0 r0.5
Keystone5005 [mil] "Keystone Compact loops"
  round 87 hole 63: 1(0,0)
  silkscreen extent -70,-70 70,70, body extent -63,-63 62,63, height 225
Keystone5006 [mil] "Keystone Compact loops"
  round 87 hole 63: 1(0,0)
  silkscreen extent -70,-70 70,70, body extent -63,-63 62,63, height 225
Keystone5007 [mil] "Keystone Compact loops"
  round 87 hole 63: 1(0,0)
  silkscreen extent -70,-70 70,70, body extent -63,-63 62,63, height 225
Keystone_575-4 [mm] "Banana Jack"
  round 10 hole 5.45: 1(0,0)
  body extent -3.95,-3.95 3.92,3.93, height 2.36
Keystone_1902C [mil] "Hex Standoff, 4-40 threaded, nylon"
  round 1 on Mech4: 0(0,0)
  body extent -145,-126 146,126, height 501
Net-Tie_10mil [mil] "10mil net tie, no solder mask opening, no solder paste"
  rect 10x10 smd paste-5 mask-5: 1(-10,0) 2(10,0)
  Top Layer region: -6,5 6,5 6,-5 -6,-5
"NY PMS 440 0025 PH" [mm] "4-40 nylon screw and mounting hole"
  round 8 hole 3.2: 1(0,0)
  body extent -3.3,-3.3 3.3,3.3, height 2.69
PG-TDSON-8 [mm] "Infineon recommended land pattern"
  rect 1.2x0.65 smd: 1(-2.825,1.905) 2(-2.825,0.635) 3(-2.825,-0.635) 4(-2.825,-1.905)
  rect 0.5x0.7 smd: 5(3.175,-2) 6(3.175,-0.675) 7(3.175,0.675) 8(3.175,2)
  rect 4.5x4.7 smd paste-2.25: 9(0.675,0)
  silkscreen extent -3.74,-3 3.74,3, body extent -3.17,-2.89 3.17,2.9, height 1.1
RHF0028A [mm] "QFN, 28-Leads, Body 5x4mm, Pitch 0.5mm, Thermal Pad 3.55x2.55mm"
  rrect42% 0.6x0.24 smd: 1(-1.9,1.75) 2(-1.9,1.25) 3(-1.9,0.75) 4(-1.9,0.25) 5(-1.9,-0.25) 6(-1.9,-0.75) 7(-1.9,-1.25) 8(-1.9,-1.75) 15(1.9,-1.75) 16(1.9,-1.25) 17(1.9,-0.75) 18(1.9,-0.25) 19(1.9,0.25) 20(1.9,0.75) 21(1.9,1.25) 22(1.9,1.75)
  rrect42% 0.24x0.6 smd: 9(-1.25,-2.4) 10(-0.75,-2.4) 11(-0.25,-2.4) 12(0.25,-2.4) 13(0.75,-2.4) 14(1.25,-2.4) 23(1.25,2.4) 24(0.75,2.4) 25(0.25,2.4) 26(-0.25,2.4) 27(-0.75,2.4) 28(-1.25,2.4)
  rrect9% 1.13x1.53 on Bottom Paste: 29(-0.665,-0.865) 29(-0.665,0.865) 29(0.665,-0.865) 29(0.665,0.865)
  rrect4% 2.55x3.55 smd paste-3.55: 29(0,0)
  silkscreen extent -2.2,-2.7 2.2,2.7, body extent -2,-2.5 2,2.5, height 1
SMA [mm] "Molded Diode, 2-Leads, Body 4.3x2.6mm, IPC Medium Density, based on OnSemi component dimensions and land pattern"
  rect 2x2 smd: 1(-2,0) 2(2,0)
  silkscreen extent -3.66,-1.57 2.79,1.57, body extent -2.6,-1.3 2.6,1.3, height 2.42
SOD-323 [mm] "NXP recommended land pattern"
  rect 0.6x0.6 smd paste-0.05: 1(-1.1,0) 2(1.1,0)
  silkscreen extent -2.06,-0.86 1.53,0.86, body extent -1.3,-0.67 1.3,0.68, height 1.1
SOD-323F [mm] "NXP recommended land pattern"
  rect 0.6x0.6 smd paste-0.05: 1(-1.1,0) 2(1.1,0)
  silkscreen extent -2.06,-0.86 1.53,0.86, body extent -1.35,-0.67 1.35,0.67, height 0.79
Sullins_PBC02SAAN [mm] "Sullins 100mil, 1x2, 230 mil above insulator"
  rect 1.65x1.65 hole 1.016: 1(0,1.27)
  round 1.65 hole 1.016: 2(0,-1.27)
  silkscreen extent -1.37,-2.54 1.27,3.1, body extent -1.27,-2.54 1.27,2.54, height 8.38
Sullins_PxC06SAAN [mm] "Header, 2.54mm, 6x1, TH"
  rect 1.55x1.55 hole 1.016: 1(-6.35,0)
  round 1.55 hole 1.016: 2(-3.81,0) 3(-1.27,0) 4(1.27,0) 5(3.81,0) 6(6.35,0)
  silkscreen extent -7.62,-1.27 7.62,1.6, body extent -7.62,-1.27 7.62,1.27, height 8.38
SW_CJS_1201A [mm] "Copal- Electronics"
  rect 1x1.6 smd paste+0 mask+0.05: 1(-1.75,-1.15) 2(0,1.15) 3(1.75,-1.15)
  silkscreen extent -3,-1.6 -2.7,-0.8, body extent -3,-1.55 3,1.55, height 2.51
XAL1510 [mm] "COILCRAFT"
  rect 3.18x14.1 smd: 1(-5.3,0) 2(5.3,0)
  silkscreen extent -7.8,-8.3 7.8,8.2, body extent -7.7,-8.2 7.7,8.2, height 11

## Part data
C1: library part CMP-0012275-3, "CAP, Aluminum Polymer, 68 uF, 63 V, +/- 20%, 0.028 ohm, 2-Pin SMD, Body 10.3 x 10.3 mm, Height 10 mm SMD", Cap_Case=10x10, Manufacturer=Nichicon, PartNumber=PCR1J680MCL1GS, Supplier Part Number 1=493-13782-1-ND, Tolerance_%=20%, Value1="0.028 ohm", Value2=63V, ValueDisplayed=68uF
C2 C3 C4 C5 C6: library part CMP-0009134-2, "CAP, CERM, 4.7 uF, 100 V, +/- 10%, X7S, 1210", Cap_Case=1210_220, Manufacturer=TDK, PartNumber=C3225X7S2A475K200AB, Supplier Part Number 1=445-6042-1-ND, TempCo=X7S, Tolerance_%=10%, Value1="0.004236 ohm", Value2=100V, ValueDisplayed=4.7uF
C7 C17: library part CMP-0008462-2, "CAP, CERM, 100 pF, 100 V, +/- 5%, C0G/NP0, 1206", Cap_Case=1206, Manufacturer=AVX, PartNumber=12061A101JAT2A, Supplier Part Number 1=478-1444-1-ND, TempCo=C0G/NP0, Tolerance_%=5%, Value1="0.701 ohm", Value2=100V, ValueDisplayed=100pF
C8 C9 C10 C11 C12 C13 C14: library part CMP-0009226-3, "CAP, CERM, 10 uF, 50 V, +/- 10%, X7R, 1210", Cap_Case=1210, Manufacturer=MuRata, PartNumber=GRM32ER71H106KA12L, Supplier Part Number 1=490-6544-1-ND, TempCo=X7R, Tolerance_%=10%, Value1=Unknown, Value2=50V, ValueDisplayed=10uF
C15 C16: library part CMP-0012273-3, "CAP, Aluminum Polymer, 180 uF, 50 V, +/- 20%, 0.019 ohm, SMD, 2-Leads, Dia 10.5mm, Pin Spacing 8mm SMD", Cap_Case=10x12.7mm, Manufacturer=Nichicon, PartNumber=PCR1H181MCL1GS, Supplier Part Number 1=493-13774-1-ND, Tolerance_%=20%, Value1="0.019 ohm", Value2=50V, ValueDisplayed=180uF
C18: library part CMP-0007220-4, "CAP, CERM, 47 pF, 50 V, +/- 5%, C0G/NP0, 0603", Cap_Case=0603, Manufacturer=MuRata, PartNumber=GRM1885C1H470JA01D, Supplier Part Number 1=490-1419-1-ND, TempCo=C0G/NP0, Tolerance_%=5%, Value1=Unknown, Value2=50V, ValueDisplayed=47pF
C19 C32: library part CMP-0007405-4, "CAP, CERM, 1 uF, 25 V, +/- 10%, X7R, 0603", Cap_Case=0603, Manufacturer=MuRata, PartNumber=GRM188R71E105KA12D, Supplier Part Number 1=490-5307-1-ND, TempCo=X7R, Tolerance_%=10%, Value1=Unknown, Value2=25V, ValueDisplayed=1uF
C20 C21 C23 C24 C25: library part CMP-0007469-4, "CAP, CERM, 0.1 uF, 100 V, +/- 10%, X7R, 0603", Cap_Case=0603, Manufacturer=MuRata, PartNumber=GRM188R72A104KA35D, Supplier Part Number 1=490-3285-1-ND, TempCo=X7R, Tolerance_%=10%, Value1=Unknown, Value2=100V, ValueDisplayed=0.1uF
C22 C29 C30 C33: library part CMP-0007237-4, "CAP, CERM, 100 pF, 100 V, +/- 5%, C0G/NP0, 0603", Cap_Case=0603, Manufacturer=MuRata, PartNumber=GRM1885C2A101JA01D, Supplier Part Number 1=490-1351-1-ND, TempCo=C0G/NP0, Tolerance_%=5%, Value1=Unknown, Value2=100V, ValueDisplayed=100pF
C26 C27: library part CMP-0007220-4, "CAP, CERM, 47 pF, 50 V, +/- 5%, C0G/NP0, 0603", Cap_Case=0603, Manufacturer=MuRata, PartNumber=GRM1885C1H470JA01D, Supplier Part Number 1=490-1419-1-ND, TempCo=C0G/NP0, Tolerance_%=5%, Value1=Unknown, Value2=50V
C28 C31: library part CMP-0006901-4, "CAP, CERM, 0.022 uF, 50 V, +/- 10%, X7R, 0603", Cap_Case=0603, Manufacturer=Kemet, PartNumber=C0603C223K5RACTU, Supplier Part Number 1=399-1280-1-ND, TempCo=X7R, Tolerance_%=10%, Value1=Unknown, Value2=50V, ValueDisplayed=0.022uF
D1: library part CMP-0077009-1, "Diode, Schottky, 20 V, 5 A, SMA", Manufacturer=Rohm, PartNumber=RSX501L-20TE25, Supplier Part Number 1=RSX501L-20TE25CT-ND, Value1=5A, Value2=0.39V
D2: library part CMP-0077010-1, "Diode, Schottky, 60 V, 3 A, SMA", Manufacturer=Rohm, PartNumber=RB050L-60TE25, Supplier Part Number 1=RB050L-60TE25CT-ND, Value1=3A, Value2=0.56V
D3: library part CMP-0077011-1, "Diode, Schottky, 60 V, 1 A, SOD-323F", Manufacturer=Nexperia, PartNumber=PMEG6010CEJ,115, Supplier Part Number 1=568-4138-1-ND, Value1=1A, Value2=0.66V
D4 D5: library part CMP-0029006-1, "Diode, Ultrafast, 100 V, 0.25 A, SOD-323", Manufacturer=Nexperia, PartNumber=BAS316,115, Supplier Part Number 1=568-5003-1-ND, Value1=0.25A, Value2=1.4V
FID1 FID2 FID3 FID4 FID5 FID6: library part CMP-0077181-1, "Fiducial mark.  There is nothing to buy or mount.", Manufacturer=N/A
H1 H2 H3 H4: library part CMP-0003617-1, "Machine Screw, Round, #4-40 x 1/4, Nylon, Philips panhead", Manufacturer="B&F Fastener Supply", Supplier Part Number 1=H542-ND
H5 H6 H7 H8: library part CMP-0003610-1, "Standoff, Hex, 0.5\"L #4-40 Nylon", Manufacturer=Keystone, PartNumber=1902C, Supplier Part Number 1=36-1902C-ND
J1 J2 J3 J4: library part CMP-0055165-2, "Standard Banana Jack, Uninsulated, 5.5mm", Manufacturer=Keystone, Supplier Part Number 1=36-575-4-ND
J5 J7: library part CMP-0054566-1, "Header, 100mil, 2x1, Gold, TH", Color=Black, Current_A=3A, Manufacturer="Sullins Connector Solutions", PartNumber=PBC02SAAN, Supplier Part Number 1=S1011E-02-ND, Voltage_V=1.8kV
J6: library part CMP-0054603-1, "Header, 2.54mm, 6x1, Gold, TH", Color=Black, Current_A=3A, Manufacturer="Sullins Connector Solutions", Supplier Part Number 1=S1011E-06-ND
L1: library part CMP-0060970-1, "Inductor, Shielded, Composite, 4.7 uH, 29 A, 0.00335 ohm, SMD", Manufacturer=Coilcraft, PartNumber=XAL1510-472MEB, Value1="0.00335 ohm", Value2=29A, ValueDisplayed=4.7uH
NT1: library part CMP-0078142-2, "Single point connection between nets.", Manufacturer=N/A
Q1 Q2 Q3 Q4: library part CMP-0000784-1, "MOSFET, N-CH, 60 V, 19 A, PG-TDSON-8", Alternate Manufacturer=None, Manufacturer="Infineon Technologies", Supplier Part Number 1=BSC039N06NSCT-ND, Value2="27 nC"
R1 R2: library part CMP-0015368-2, "RES, 0, 5%, 2 W, 2512 WIDE", Manufacturer="Vishay Draloric", PartNumber=RCL12250000Z0EG, Power_W=2W, Supplier Part Number 1=RCL0.0ECT-ND, TempCo=ppm/C, Tolerance_%=5%, Value_Code=0000, ValueDisplayed=0
R3 R4 R6 R7 R15 R17: library part CMP-0025885-5, "RES, 0, 5%, 0.1 W, 0603", Manufacturer=Yageo, PartNumber=RC0603JR-070RL, Power_W=100mW, Supplier Part Number 1=311-0.0GRCT-ND, TempCo="200 ppm/C", Tolerance_%=5%, Value2=0.1W, Value_Code=0000, ValueDisplayed=0
R5 R8: library part CMP-0018578-3, "RES, 10, 5%, 0.25 W, AEC-Q200 Grade 0, 1206", Manufacturer=Vishay-Dale, PartNumber=CRCW120610R0JNEA, Power_W=250mW, Supplier Part Number 1=541-10ECT-ND, TempCo="200 ppm/C", Tolerance_%=5%, Value2=0.25W, Value_Code=10R0, ValueDisplayed=10
R9 R11: library part CMP-0022736-4, "RES, 100, 1%, 0.1 W, 0603", Manufacturer=Yageo, PartNumber=RC0603FR-07100RL, Power_W=100mW, Supplier Part Number 1=311-100HRCT-ND, TempCo="100 ppm/C", Tolerance_%=1%, Value2=0.1W, Value_Code=100R, ValueDisplayed=100
R10: library part CMP-0015114-2, "RES, 0.008, 1%, 4 W, 3015 WIDE", Manufacturer="Susumu Co Ltd", PartNumber=KRL7638-C-R008-F-T1, Power_W=4W, Supplier Part Number 1=KRL76C.008CT-ND, TempCo="50 ppm/C", Tolerance_%=1%, Value_Code=8L000, ValueDisplayed=0.008
R12 R14: library part CMP-0022751-4, "RES, 10.0, 1%, 0.1 W, 0603", Manufacturer=Yageo, PartNumber=RC0603FR-0710RL, Power_W=100mW, Supplier Part Number 1=311-10.0HRCT-ND, TempCo="100 ppm/C", Tolerance_%=1%, Value2=0.1W, Value_Code=10R0, ValueDisplayed=10.0
R13: library part CMP-0022268-4, "RES, 2.00 k, 1%, 0.1 W, AEC-Q200 Grade 0, 0603", Manufacturer=Vishay-Dale, Power_W=100mW, Supplier Part Number 1=541-2.00KHCT-ND, TempCo="100 ppm/C", Tolerance_%=1%, Value2=0.1W, Value_Code=2k00, ValueDisplayed=2.00k
R16: library part CMP-0022941-4, "RES, 249 k, 1%, 0.1 W, 0603", Manufacturer=Yageo, PartNumber=RC0603FR-07249KL, Power_W=100mW, Supplier Part Number 1=311-249KHRCT-ND, TempCo="100 ppm/C", Tolerance_%=1%, Value2=0.1W, Value_Code=249k
R18 R26: library part CMP-0022746-5, "RES, 10.0 k, 1%, 0.1 W, 0603", Manufacturer=Yageo, PartNumber=RC0603FR-0710KL, Power_W=100mW, Supplier Part Number 1=311-10.0KHRCT-ND, TempCo="100 ppm/C", Tolerance_%=1%, Value2=0.1W, Value_Code=10k0, ValueDisplayed=10.0k
R19: library part CMP-0022969-4, "RES, 280 k, 1%, 0.1 W, 0603", Manufacturer=Yageo, PartNumber=RC0603FR-07280KL, Power_W=100mW, Supplier Part Number 1=311-280KHRCT-ND, TempCo="100 ppm/C", Tolerance_%=1%, Value2=0.1W, Value_Code=280k
R20 R23 R27 R28: library part CMP-0021991-4, "RES, 100, 1%, 0.1 W, AEC-Q200 Grade 0, 0603", Manufacturer=Vishay-Dale, PartNumber=CRCW0603100RFKEA, Power_W=100mW, Supplier Part Number 1=541-100HCT-ND, TempCo="100 ppm/C", Tolerance_%=1%, Value2=0.1W, Value_Code=100R, ValueDisplayed=100
R21: library part CMP-0023195-5, "RES, 59.0 k, 1%, 0.1 W, 0603", Manufacturer=Yageo, PartNumber=RC0603FR-0759KL, Power_W=100mW, Supplier Part Number 1=311-59.0KHRCT-ND, TempCo="100 ppm/C", Tolerance_%=1%, Value2=0.1W, Value_Code=59k0, ValueDisplayed=59.0k
R22: library part CMP-0023322-5, "RES, 93.1 k, 1%, 0.1 W, 0603", Manufacturer=Yageo, PartNumber=RC0603FR-0793K1L, Power_W=100mW, Supplier Part Number 1=311-93.1KHRCT-ND, TempCo="100 ppm/C", Tolerance_%=1%, Value2=0.1W, Value_Code=93k1, ValueDisplayed=93.1k
R24: library part CMP-0022906-5, "RES, 20.0 k, 1%, 0.1 W, 0603", Manufacturer=Yageo, PartNumber=RC0603FR-0720KL, Power_W=100mW, Supplier Part Number 1=311-20.0KHRCT-ND, TempCo="100 ppm/C", Tolerance_%=1%, Value2=0.1W, Value_Code=20k0, ValueDisplayed=20.0k
R25: library part CMP-0022254-4, "RES, 27.4 k, 1%, 0.1 W, AEC-Q200 Grade 0, 0603", Manufacturer=Vishay-Dale, Power_W=100mW, Supplier Part Number 1=541-27.4KHCT-ND, TempCo="100 ppm/C", Tolerance_%=1%, Value2=0.1W, Value_Code=27k4, ValueDisplayed=27.4k
S1: library part CMP-0002159-2, "Slide SW, SPDT 0.1A 50VDC", CurrentRating_mA=100A, Manufacturer="Copal Electronics", PartNumber=CJS-1201TA, Supplier Part Number 1=563-1023-1-ND
TP1 TP2: library part CMP-0055142-1, "Test Point, Compact, Red, TH", Color=Red, Manufacturer=Keystone, Supplier Part Number 1=36-5005-ND
TP3 TP4: library part CMP-0055143-1, "Test Point, Compact, Black, TH", Color=Black, Manufacturer=Keystone, Supplier Part Number 1=36-5006-ND
TP5: library part CMP-0055144-1, "Test Point, Compact, White, TH", Color=White, Manufacturer=Keystone, Supplier Part Number 1=36-5007-ND
U1: library part CMP-0084180-1, "30-V Wide VIN Synchronous 4-Switch Buck-Boost Controller, RHF0028A (VQFN-28)", Alternate Manufacturer="Texas Instruments", Alternate PartNumber=LM34936RHFT
ZZ2: library part CMP-0077236-1
ZZ3: library part CMP-0077237-1
ZZ4: library part CMP-0077238-1
ZZ5 ZZ6 ZZ7: library part AssemblyNote, Alternate Manufacturer=-

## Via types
v1: diameter 24, hole 10, Top Layer to Bottom Layer, tented both sides, 212 vias
v2: diameter 24, hole 10, Top Layer to Bottom Layer, 124 vias
v3: diameter 19.68, hole 7.87, Top Layer to Bottom Layer, 9 vias
v4: diameter 24, hole 14, Top Layer to Bottom Layer, 3 vias
v5: diameter 38, hole 24, Top Layer to Bottom Layer, 2 vias
v6: diameter 24, hole 14, Top Layer to Bottom Layer, tented both sides, 2 vias

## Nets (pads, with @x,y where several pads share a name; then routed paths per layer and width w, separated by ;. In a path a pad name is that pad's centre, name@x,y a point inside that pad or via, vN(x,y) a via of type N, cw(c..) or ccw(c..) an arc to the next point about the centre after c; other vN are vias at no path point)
AGND: C25.2 C26.2 C27.2 C29.2 C30.2 C31.2 C33.2 J5.2 NT1.2 R21.1 R22.1 R24.1 R25.1 R26.1 S1.1 U1.7 | length 399.3
  Bottom Layer w10: U1.7@2159.8,1741.42 2181.58,1741.42 2194,1729 2201,1729 ; R24.1@2477.5,1690.63 2513.63,1690.63
  Bottom Layer w16: 2201,1729 2201.16,1728.84 2454.14,1728.84 2454.96,1728.02 2516,1728.02
  Bottom Layer w24: S1.1@2891.1,2070.28 S1.1@2892.1,2069.28
BIAS: C24.1 R17.2 TP5.1 U1.21 | length 1737.7
  Top Layer w12: v1(1913,1854) 1914.69,1855.69 C24.1@1958.62,1855.69
  MidLayer3 w12: v1(1913,1854) 1950,1817 1950,1652 2047,1555 v1(2410,1555)
  Bottom Layer w9: 1987.56,1839.84 U1.21@2010.2,1839.84
  Bottom Layer w12: v1(1913,1854) 1973.4,1854 1987.56,1839.84 ; v1(2410,1555) 2407.44,1552.44 R17.2@2407.44,1410 2407.44,916.56 TP5.1@2571,753
BOOT1: C21.2 D4.1 U1.23 | length 277.1
  Bottom Layer w10: D4.1@1806.31,1936 1998,1936 C21.2@2001,1939 2023,1939 2035.79,1926.21 U1.23@2035.79,1885.12
BOOT2: C23.1 D5.1 U1.17 | length 409.1
  Bottom Layer w9: 1972.8,1752.24 1972.9,1752.14 1973.14,1752.14 1982.1,1761.1 U1.17@2010.2,1761.1
  Bottom Layer w12: D5.1@1698,1734.69 1730.31,1734.69 1745,1720 C23.1@1834,1720 C23.1@1840,1720 ; 1766.44,1719.56 C23.1@1834,1719.56 ; C23.1@1832.56,1712.56 C23.1@1840,1720 ; 1969.68,1749.13 1950,1749.13 1929.87,1729 1869,1729 1860,1720 C23.1@1840,1720
COMP: C28.1 C30.1 J6.4 U1.6 | length 1420.6
  MidLayer3 w10: v1@2388,1760.46 2659.54,1760.46 2692,1728 3387,1728 3400,1715 J6.4@3465,1715
  Bottom Layer w9: U1.6@2159.8,1761.1 2188.35,1761.1
  Bottom Layer w10: 2188.35,1761.1 2197.2,1752.24 2337.24,1752.24 2345.46,1760.46 C28.1@2423.19,1760.46 2477.27,1760.46 C30.1@2477.44,1760.63
  other v1: 2383,1760.46
CS: C18.1 R9.1 U1.13 | length 190.7
  Bottom Layer w9: R9.1@2013,1523 2013.44,1523.44 C18.1@2013.44,1588 2013.44,1618.44 2055.47,1660.47 2055.47,1673.47 U1.13@2055.47,1696.14
CSG: C18.2 R11.1 U1.12 | length 184.9
  Bottom Layer w9: 2075.16,1680.94 U1.12@2075.16,1696.14
  Bottom Layer w10: R11.1@2068,1524 2068.56,1524.56 C18.2@2068.56,1588 2075.16,1594.6 2075.16,1643.16 ; 2075.16,1653 2075.16,1643.16 ; 2075.16,1680.94 2075.16,1643.16
DITHER: C31.1 S1.2 U1.2 | length 954.9
  MidLayer3 w10: v1(2430,2013.43) 2566.57,2013.43 2600,1980 v1(2907,1980)
  Bottom Layer w9: U1.2@2159.8,1839.84 2175,1839.84 2181,1845.84 ; v1(2907,1980) 2908.28,1978.72 S1.2@2961,1978.72
  Bottom Layer w10: 2181,1845.84 2189.77,1854.61 2273.7,1854.61 2274.85,1855.76 2275.3,1855.76 2309,1889.45 2309,1925 2397.43,2013.43 v1(2430,2013.43) C31.1@2474.64,2013.43 ; v1(2907,1980) v1@2909,1980
EN: C27.1 J5.1 R16.1 R21.2 U1.26 | length 994.3
  MidLayer3 w10: v1(2120,1990) 2284.37,1990 2359.37,2065 v1(2425,2065) ; v1(2477.44,2154) 2590,2154 2727,2291 J5.1@2782,2291
  Bottom Layer w8: U1.26@2094.84,1885.12 2094.84,1905.84 2120.92,1931.92 2120.92,1989.08 v1(2120,1990)
  Bottom Layer w10: v1(2425,2065) R21.2@2477.44,2065 C27.1@2477.44,2115 v1(2477.44,2154) 2477.44,2162.56 2475,2165 R16.1@2475,2192.44
FB: R19.1 R24.2 U1.8 | length 327.3
  Bottom Layer w9: U1.8@2159.8,1721.73 2160.07,1722 2174,1722 ; 2174.89,1722 2174,1722 ; 2201,1701.06 2194.94,1701.06 2174,1722
  Bottom Layer w10: 2201,1701.06 2384.57,1701.06 2395,1690.63 R24.2@2422.38,1690.63 R24.2@2422.38,1690.63 R19.1@2422.44,1640
GND: C1.2 C2.2 C3.2 C4.2 C5.2 C6.2 C8.2 C9.2 C10.2 C11.2 C12.2 C13.2 C14.2 C15.2 C16.2 C19.1 C20.2 C24.2 J3.1 J4.1 J6.6 NT1.1 R10.1 R11.2 TP3.1 TP4.1 U1.19 U1.29@2085,1790.63 | length 2280.9
  Top Layer w10: C1.2@1694.7,2868 2069,2868 TP3.1@2070,2867 ; v2(1722.48,758) 2113,758 TP4.1@2114,759
  Top Layer w16: v1(1909,1802) 1918.3,1792.7 C24.2@1958.62,1792.7
  MidLayer3 w10: v1(1591,1801) 1571.87,1781.87 1571.87,1644.13 1581,1635 1700,1635 1887.13,1447.87 2043.13,1447.87 v1(2068,1423)
  Bottom Layer w9: 1962.33,1800.47 U1.19@2010.2,1800.47 2045.23,1800.47 2045.53,1800.17 U1.29@2061.29,1800.33 ; v3(2085,1790.63) v3(2085,1849.69)
  Bottom Layer w10: C14.2@1622.09,758 v2(1722.48,758) ; C20.2@2162,2034.56 v1(2162,2071)
  Bottom Layer w16: v1@1590,1801.16 1642.84,1801.16 1662.5,1781.5 v1(1752,1781.5) C19.1@1812,1781.5 ; 1833.7,1781.5 1850.5,1781.5 1871,1802 v1(1909,1802) 1962.2,1802 1962.33,1801.87 ; v1(2068,1423) R11.2@2068,1468
  other v1: 1839,709 1873,709 1907,709 1942,709 1977,709 2012,709 1838,810 1872,810 1906,810 1941,810 1976,810 2011,810 1675,1249 1675,1282 1675,1315 1737,1326 1771,1326 1805,1326 1840,1326 1738,1368 1772,1368 1806,1368 1841,1368 1675,1387 1675,1420 1675,1545 1675,1584 1596,1664 1676,1683 1712,1683 1596,1697 1596,1762 1716,1780.5 1591,1842 1677,1852 1740,1852 1591,1878 1673,1932 1591,1940 1675,2004 1675,2037 1675,2074 1675,2157 1675,2190 1675,2222 1675,2275 1675,2316 1675,2357 2175,2826 2208,2826 2241,2826 2274,2826 2308,2826 1821,2838 1854,2838 1887,2838 1920,2838 1954,2838 2176,2866 2209,2866 2242,2866 2275,2866 2309,2866 1822,2897 1855,2897 1888,2897 1921,2897 1955,2897 2177,2907 2210,2907 2243,2907 2276,2907 2310,2907
  other v2: 1619,1249 1619.09,1282 1619,1315 1621.99,1387 1621.99,1420 1617.99,1545 1617.99,1584 1620,2010 1621,2043 1620.63,2077.28 1619,2157 1619,2190 1620,2225 1619,2282 1620,2325 1620,2360
  other v3: 2046,1731 2125,1731 2085,1731.57 2045.63,1790.63 2124.37,1790.63 2046,1850 2125,1850
HO1: R3.2 U1.24 | length 184.9
  Bottom Layer w9: R3.2@1939,1966.44 1939.07,1966.37 2031.37,1966.37 2032,1967 2055.47,1943.53 U1.24@2055.47,1885.12
HO2: R4.2 U1.16 | length 1207.4
  Top Layer w25: R4.2@1073,1274.44 1074.44,1273 v1(1109,1273)
  MidLayer1 w20: v1(1109,1273) 1203.13,1367.13 1384.21,1367.13 1387.08,1370
  MidLayer1 w24: 1387.08,1370 1405,1387.92 1405,1411 1448,1454 1739,1454 1833,1548 1833,1654 v4(1878,1699)
  Bottom Layer w9: 1957.88,1722.12 1962.41,1726.65 1976.65,1726.65 1991.42,1741.42 U1.16@2010.2,1741.42
  Bottom Layer w20: v4(1878,1699) 1934.75,1699 1957.88,1722.12
INSNS+: C1.1 J1.1 R1.1 R28.2 TP1.1 | length 2923.3
  Top Layer w8: TP1.1@1068,2867 1069,2868 C1.1@1407.3,2868
  MidLayer1 w8: v1(2143,1415) 2165,1393 2331.45,1393 2601.87,1663.42 2601.87,2230.11 2620,2248.24 v1(2620,2249)
  MidLayer3 w8: v2(1377,2558) 1403.13,2531.87 2339.13,2531.87 v1@2614.5,2256.5
  Bottom Layer w10: R28.2@2139,1461.5 2143,1457.5 v1(2143,1415)
  other v1: 814,2822 847,2822 880,2822 913,2822 947,2822 1161,2838 1194,2838 1227,2838 1260,2838 1294,2838 815,2862 848,2862 881,2862 914,2862 948,2862 1162,2897 1195,2897 1228,2897 1261,2897 1295,2897 816,2903 849,2903 882,2903 915,2903 949,2903
  other v2: 1415,2556 1447.33,2556 1479.67,2556 1512,2556 1244,2558 1277,2558 1310,2558 1343,2558
INSNS-: C2.1 C3.1 C4.1 C5.1 C6.1 D3.2 Q1.5 Q1.6 Q1.7 Q1.8 Q1.9 R1.2 R13.2 R16.2 R20.2 | length 2747.2
  Top Layer w8: R1.2@1377,2495 v2(1378,2496)
  MidLayer1 w8: v1(2309,1422) 2338,1422 2586,1670 v1(2586,2248)
  MidLayer3 w8: v2(1378,2496) 1398,2516 2332.55,2516 2586,2262.55 v1(2586,2248)
  Bottom Layer w8: D3.2@2217,2187.31 2302.25,2187.31 R13.2@2303,2186.56 2303,2205.31
  Bottom Layer w12: 2303,2205.31 2303,2211 2339.56,2247.56 R16.2@2475,2247.56 2585.56,2247.56 v1(2586,2248) ; R20.2@2308,1464.73 2309,1463.73 v1(2309,1422)
  other v1: 1461,2011
  other v2: 1505,2010 1505,2043 1461,2045 1504.63,2077.28 1461,2078 1505,2157 1455,2160 1307,2181 1360,2181 1256,2182 1505,2190 1455,2195 1505,2225 1360,2226 1256,2227 1307,2227 1455,2230 1256,2276 1307,2276 1360,2276 1455,2280 1505,2280 1455,2315 1505,2315 1455,2350 1505,2350 1415,2495 1447.33,2495 1479.67,2495 1512,2495 1244,2497 1277,2497 1310,2497 1343,2497
LO1: R6.2 U1.22 | length 729.9
  MidLayer1 w15: 1517,1909 1613,1909
  MidLayer1 w24: 1613,1909 1637,1885 v6(1860,1885)
  MidLayer1 w25: v1(1422,1991) 1435,1991 1517,1909
  Bottom Layer w12: v6(1860,1885) 1860.75,1884.25 1974.75,1884.25 U1.22@1999.47,1859.53
  Bottom Layer w25: v1(1422,1991) 1422,2085.56 1424,2087.56 R6.2@1423.56,2088
LO2: R7.2 U1.18 | length 628.5
  MidLayer1 w24: v1(1446.56,1742.44) 1458.87,1730.13 1625.13,1730.13 1641.87,1746.87 1866.87,1746.87 1878,1758 v4(1907,1758)
  Bottom Layer w9: 1966.17,1780 1967.17,1781 1977.71,1781 1977.92,1780.79 U1.18@2010.2,1780.79
  Bottom Layer w12: v4(1907,1758) 1921,1758 1943,1780 1966.17,1780
  Bottom Layer w24: v1(1446.56,1742.44) R7.2@1446.56,1781
MODE: C26.1 J6.3 J7.2 R22.2 U1.1 | length 1606
  MidLayer3 w10: v2(2265,1880.63) 2737.37,1880.63 2841,1777 v1@2908,1777 ; v1(2910,1777) 3382,1777 3417,1812 J6.3@3467,1812
  Bottom Layer w9: U1.1@2159.8,1859.53 U1.1@2169.41,1859.53 ; v1(2910,1777) v1@2910.28,1776.72
  Bottom Layer w10: U1.1@2169.41,1859.53 2190.08,1880.2 2264.57,1880.2 v2(2265,1880.63) ; R22.2@2782.56,1920.63 C26.1@2782.56,1870.63 2782.56,1836.44 2842,1777 v1@2908,1777
NetC7_2: C7.2 R5.2 | length 148.4
  Bottom Layer w12: R5.2@994,1339.91 1134,1339.91 C7.2@1139.91,1334
NetC17_2: C17.2 R8.2 | length 96.4
  Bottom Layer w12: C17.2@1057,2089.09 1151.83,2089.09 R8.2@1152.91,2088
NetC20_1: C20.1 R12.1 U1.27 | length 169.4
  Bottom Layer w9: U1.27@2114.53,1885.12 2114.53,1901.53 2160,1947 2160,1977.44 C20.1@2162,1979.44 2216,1979.44 R12.1@2217,1980.44
NetC22_2: C22.2 R25.2 U1.3 | length 1112.4
  MidLayer3 w10: v1(2400,1963) 2400,2019 2420,2039 2789,2039 2900,2150 v1(2965,2150)
  Bottom Layer w9: U1.3@2159.8,1820.16 2181.16,1820.16 2190.02,1829.02
  Bottom Layer w10: 2190.02,1829.02 2197.2,1829.02 2284.02,1829.02 2338,1883 2338,1902 v1@2399.43,1963.43 ; v1@2400,1963.43 R25.2@2474.64,1963.43 ; v1(2965,2150) C22.2@3017.44,2150
NetC28_2: C28.2 R26.2 | length 44.9
  Bottom Layer w10: C28.2@2432.56,1810.63 R26.2@2477.44,1810.63
NetC32_1: C32.1 R20.1 R23.1 U1.10 | length 322.1
  Bottom Layer w9: 2114.53,1667.47 U1.10@2114.53,1696.14
  Bottom Layer w10: 2114.53,1667.47 2132.12,1649.88 2191,1649.88 2239.56,1601.32 C32.1@2239.56,1569.7 2246.45,1562.81 2246.45,1527.54 R23.1@2253,1520.99 2307.74,1520.99 R20.1@2308,1520.73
